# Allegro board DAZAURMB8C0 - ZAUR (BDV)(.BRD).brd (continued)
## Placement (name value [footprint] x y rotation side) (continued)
R194  HDT@1K_1%_2  [R0201]  117.79 48.73 0 top
R195  *1K_1%_2  [R0201]  114.74 48.5 90 top
R196  *2K_1%_2  [R0201]  115.45 48.5 270 top
R197  HDT@1K_1%_2  [R0201]  117.79 47.97 0 top
R198  TPC@100K_5%_4  [R0402]  23.94 47.87 180 top
R199  TPC@20K_1%_2  [R0201]  16.44 47.41 0 top
R200  **100K_1%_4  [R0402]  115.25 47.41 180 top
R201  *1K_1%_4  [R0402]  115.1 46.01 90 top
R202  **10K_5%_4  [R0402]  116.8 47.51 270 top
R203  HDT@1K_1%_2  [R0201]  117.79 46.98 0 top
R204  TPC@0_5%_2  [R0201]  22.03 46.34 180 top
R205  TPC_N@0_5%_2  [R0201]  22.48 46.34 0 top
R206  HDT@1K_1%_2  [R0201]  117.79 46.21 0 top
R207  TPC@0_5%_2  [R0201]  22.03 45.07 180 top
R208  TPC_N@0_5%_2  [R0201]  22.48 45.07 0 top
R209  HDT@10K_1%_2  [R0201]  117.41 44.44 0 top
R210  TSI@2.2K_5%_2  [R0201]  107.76 43.8 270 top
R211  TSI@2.2K_5%_2  [R0201]  108.52 43.8 270 top
R212  SP@0_5%_2  [R0201]  36.64 43.67 180 top
R213  SP@0_5%_2  [R0201]  37.65 43.67 180 top
R214  HDT@33_5%_2  [R0201]  113.85 44.18 90 top
R215  HDT@1K_1%_2  [R0201]  114.62 44.18 270 top
R216  HDT@10K_1%_2  [R0201]  117.41 43.67 0 top
R217  240_1%_2  [R0201]  41.21 43.04 180 top
R218  SP@0_5%_2  [R0201]  43.37 43.04 180 top
R219  HDT@33_5%_2  [R0201]  116.01 42.15 90 top
R220  HDT@1K_1%_2  [R0201]  116.77 42.15 270 top
R221  1K_1%_2  [R0201]  105.34 41.06 0 top
R222  100K_5%_2  [R0201]  148.91 40.88 90 top
R223  15K_1%_4  [R0402]  113.02 41.26 180 top
R224  10K_5%_2  [R0201]  105.34 40.3 0 top
R225  *10_5%_6  [R0603]  110.63 41.52 90 top
R226  10K_5%_2  [R0201]  103.06 39.99 0 top
R227  10K_5%_2  [R0201]  105.34 39.53 0 top
R228  10K_5%_2  [R0201]  103.06 39.23 0 top
R229  *Short_0201  [S0201]  22.54 38.47 180 top
R230  10K_5%_2  [R0201]  99.88 38.47 0 top
R231  TPC_N@10K_5%_4  [R0402]  104.33 38.21 270 top
R232  TPC@10K_5%_4  [R0402]  105.85 38.21 90 top
R233  0_2  [R0201]  152.59 37.96 90 top
R234  *Short_0201  [S0201]  22.54 37.45 180 top
R235  *Short_0201  [S0201]  103.19 37.2 0 top
R236  10K_5%_2  [R0201]  104.84 36.82 0 top
R237  *Short_0201  [S0201]  21.91 35.67 180 top
R238  *Short_0201  [S0201]  21.91 34.66 180 top
R239  33_5%_2  [R0201]  160.72 34.28 90 top
R240  *Short_0603  [S0603]  99.25 34.15 270 top
R241  10K_5%_2  [R0201]  92.77 33.64 270 top
R242  MD@10K_5%_2  [R0201]  93.53 33.64 90 top
R243  MD@10K_5%_2  [R0201]  94.3 33.64 270 top
R244  *0_5%_4  [R0402]  211.64 33.13 180 top
R245  2.2_5%_6  [R0603]  162.37 32.37 180 top
R246  *10K_5%_2  [R0201]  164.53 32.37 0 top
R247  10K_5%_2  [R0201]  174.69 32.37 180 top
R248  SP@0_5%_2  [R0201]  36.95 32.24 0 top
R249  SP@0_5%_2  [R0201]  37.94 32.24 0 top
R250  4.7K_5%_2  [R0201]  173.67 32.24 180 top
R251  *Short_0201  [S0201]  177.61 32.24 90 top
R252  *Short_0201  [S0201]  178.37 32.24 90 top
R253  *Short_0201  [S0201]  179.13 32.24 90 top
R254  *Short_0201  [S0201]  179.89 32.24 90 top
R255  10K_5%_2  [R0201]  181.04 32.24 90 top
R256  33_5%_2  [R0201]  183.2 32.24 0 top
R257  GS_N@10K_5%_4  [R0402]  100.9 32.12 0 top
R258  100K_5%_2  [R0201]  170.5 32.12 90 top
R259  4.7K_5%_2  [R0201]  171.26 32.12 90 top
R260  4.7K_5%_2  [R0201]  172.02 32.12 90 top
R261  1K_1%_4  [R0402]  102.8 31.99 180 top
R262  100K_5%_4  [R0402]  104.58 31.99 180 top
R263  *10K_5%_2  [R0201]  168.34 31.99 270 top
R264  *Short_0402  [S0402]  175.7 31.86 90 top
R265  *0_4  [R0402]  176.72 31.86 270 top
R266  MD@10K_5%_4  [R0402]  107.25 31.74 270 top
R267  MD@10K_5%_4  [R0402]  108.27 31.74 90 top
R268  *Short_0402  [S0402]  199.58 31.74 0 top
R269  33_5%_2  [R0201]  164.53 31.61 180 top
R270  4.7K_5%_2  [R0201]  173.67 31.48 180 top
R271  *0_5%_4  [R0402]  209.74 31.36 180 top
R272  10K_5%_2  [R0201]  96.96 31.23 270 top
R273  240_1%_2  [R0201]  40.19 30.85 180 top
R274  SP@0_5%_2  [R0201]  41.34 30.85 180 top
R275  *0_5%_4  [R0402]  209.74 30.09 180 top
R276  0_5%_8  [R0805]  190.05 29.78 180 top
R277  *Short_0402  [S0402]  105.73 29.45 270 top
R278  **MS@0_4  [R0402]  197.93 29.07 270 top
R279  10K_5%_2  [R0201]  101.41 28.94 270 top
R280  *Short_0603  [S0603]  96.33 28.69 0 top
R281  GS@10K_5%_4  [R0402]  100.52 28.56 90 top
R282  33_5%_2  [R0201]  183.53 29.15 180 top
R283  *10K_5%_2  [R0201]  159.45 28.56 180 top
R284  *10K_5%_2  [R0201]  159.45 27.8 0 top
R285  10K_5%_2  [R0201]  163.38 26.28 270 top
R286  2.2K_5%_2  [R0201]  71.82 27.16 270 top
R287  2.2K_5%_2  [R0201]  72.58 27.16 270 top
R288  *Short_0603  [S0603]  96.33 27.16 0 top
R289  45.3K_1%_4  [R0402]  103.19 26.91 90 top
R290  1.5K_5%_4  [R0402]  104.33 26.91 270 top
R291  *Short_0603  [S0603]  92.14 26.4 0 top
R292  *Short_0402  [S0402]  197.8 26.4 0 top
R293  **0_4  [R0402]  159.32 26.53 90 top
R294  10K_5%_2  [R0201]  94.3 26.15 180 top
R295  *Short_0603  [S0603]  87.67 26.02 0 top
R296  *Short_0201  [S0201]  100.77 25.89 180 top
R297  *Short_0603  [S0603]  84.64 25.77 0 top
R298  2.2_5%_6  [R0603]  162.24 25.59 90 top
R299  *0_5%_4  [R0402]  209.23 25.39 90 top
R300  EV@10K_5%_2  [R0201]  89.47 28.03 180 top
R301  *EV@0_5%_2  [R0201]  90.18 28.76 180 top
R302  *EV@Short_0201  [S0201]  91.2 25.26 0 top
R303  33_5%_2  [R0201]  184.06 25.13 0 top
R304  *Short_0201  [S0201]  197.8 25.13 180 top
R305  *2.2_5%_6  [R0603]  160.08 24.88 180 top
R306  *0_2  [R0201]  186.5 24.88 180 top
R307  *TPM@Short_0201  [S0201]  122.11 24.75 270 top
R308  *TPM@Short_0201  [S0201]  122.87 24.75 270 top
R309  *Short_0201  [S0201]  187.51 24.75 0 top
R310  10K_5%_2  [R0201]  188.53 24.75 0 top
R311  TPM@33_5%_2  [R0201]  121.22 24.37 0 top
R312  TPM@0_4  [R0402]  132.14 24.12 270 top
R313  *10K_5%_4  [R0402]  105.22 23.99 0 top
R314  *TPC@Short_0201  [S0201]  25.08 23.86 180 top
R315  *100K_1%_2  [R0201]  197.8 23.86 180 top
R316  TPM@10K_5%_2  [R0201]  121.22 23.35 0 top
R317  *256@0_5%_2  [R0201]  200.72 23.35 0 top
R318  *255@0_5%_2  [R0201]  201.74 23.35 180 top
R319  33_5%_2  [R0201]  185.23 23.1 180 top
R320  **MS@0_4  [R0402]  199.2 23.1 270 top
R321  *TPM@Short_0201  [S0201]  121.22 22.59 0 top
R322  *22_5%_4  [R0402]  162.88 22.72 180 top
R323  *TPM@0_4  [R0402]  132.52 22.34 90 top
R324  *Short_0201  [S0201]  185.35 22.34 0 top
R325  TPM@33_5%_2  [R0201]  120.97 21.83 0 top
R326  *10_5%_6  [R0603]  149.54 21.83 180 top
R327  *10K_5%_2  [R0201]  200.85 21.83 180 top
R328  *Short_0402  [S0402]  206.55 21.83 180 top
R329  *255@0_5%_4  [R0402]  199.32 21.7 180 top
R330  *Short_0201  [S0201]  153.22 21.45 90 top
R331  100K_5%_4  [R0402]  158.3 21.96 0 top
R332  TPC@100K_5%_4  [R0402]  183.96 21.45 180 top
R333  *TPM@1.2K_5%_2  [R0201]  129.6 21.32 270 top
R334  1K_5%_2  [R0201]  201.53 20.94 270 top
R335  *TPC@Short_0402  [S0402]  20.51 20.69 0 top
R336  *TPC@4.7K_5%_2  [R0201]  15.05 20.56 270 top
R337  *TPC@Short_0201  [S0201]  15.81 20.56 90 top
R338  *TPC@10K_5%_2  [R0201]  16.7 20.56 90 top
R339  TPC_N@100K_5%_4  [R0402]  183.96 20.43 0 top
R340  *GS@Short_0402  [S0402]  61.91 20.31 180 top
R341  TPC@10K_5%_4  [R0402]  17.71 20.18 270 top
R342  TPC@10K_5%_4  [R0402]  18.73 20.18 270 top
R343  *TPM@0_4  [R0402]  131.89 20.05 90 top
R344  *Short_0603  [S0603]  199.86 20.13 180 top
R345  *TPC@Short_0201  [S0201]  24.19 19.8 180 top
R346  100K_5%_4  [R0402]  147.51 19.67 90 top
R347  10K_5%_4  [R0402]  153.22 19.67 270 top
R348  4.7K_5%_2  [R0201]  71.31 19.58 180 top
R349  4.7K_5%_2  [R0201]  72.45 19.58 0 top
R350  TPM@10K_5%_2  [R0201]  121.22 19.04 0 top
R351  100K_5%_2  [R0201]  159.57 18.4 270 top
R352  *Short_0201  [S0201]  160.46 18.53 0 top
R353  **MS@0_4  [R0402]  203.8 19.32 0 top
R354  256@0_5%_4  [R0402]  205.8 18.66 180 top
R355  TPC@220K_5%_2  [R0201]  13.4 18.53 90 top
R356  TPM@0_4  [R0402]  131.51 18.53 0 top
R357  *GS@Short_0201  [S0201]  68.64 18.38 270 top
R358  TPM@33_5%_2  [R0201]  121.22 18.27 0 top
R359  *Short_0603  [S0603]  115.43 17.97 270 top
R360  *Short_0603  [S0603]  116.9 17.97 270 top
R361  *Short_0603  [S0603]  118.32 17.97 270 top
R362  *Short_0603  [S0603]  119.75 17.97 270 top
R363  TPC@220K_5%_2  [R0201]  13.4 17.51 270 top
R364  4.7K_5%_2  [R0201]  205.17 17.44 180 top
R365  *4.7K_5%_2  [R0201]  206.18 17.51 180 top
R366  TPC@6.2K_1%_2  [R0201]  22.41 17.39 0 top
R367  ODD@10K_5%_4  [R0402]  129.09 17.51 0 top
R368  *MS@100K_5%_4  [R0402]  188.02 17.39 180 top
R369  100K_5%_2  [R0201]  183.07 17.26 0 top
R370  *255@0_5%_4  [R0402]  204.1 17.23 270 top
R371  4.7K_5%_2  [R0201]  205.17 16.72 180 top
R372  *4.7K_5%_2  [R0201]  206.18 16.75 180 top
R373  TPC@200K_1%_2  [R0201]  23.53 16.62 0 top
R374  TPC@10K_1%_2  [R0201]  22.64 16.5 90 top
R375  *ODD@10K_5%_4  [R0402]  126.5 16.88 270 top
R376  *Short_0201  [S0201]  70.93 16.27 180 top
R377  *Short_0201  [S0201]  72.83 16.27 180 top
R378  *GS@10K_5%_2  [R0201]  68.9 16.24 0 top
R379  *GS@Short_0201  [S0201]  68.01 15.99 90 top
R380  *4.7K_5%_2  [R0201]  204.4 15.99 180 top
R381  4.7K_5%_2  [R0201]  206.18 15.99 180 top
R382  ODD@0_5%_8  [R0805]  142.56 15.73 270 top
R383  TPC@220K_5%_2  [R0201]  12.13 15.66 90 top
R384  100K_5%_2  [R0201]  163.38 15.61 90 top
R385  10K_5%_4  [R0402]  159.83 15.23 90 top
R386  *GS@10K_5%_2  [R0201]  66.48 15.23 270 top
R387  *GS@Short_0201  [S0201]  67.24 15.23 90 top
R388  ODD@33_5%_2  [R0201]  127.19 15.23 270 top
R389  *4.7K_5%_2  [R0201]  204.4 15.23 180 top
R390  4.7K_5%_2  [R0201]  206.18 15.23 180 top
R391  TPC@10K_5%_4  [R0402]  22.92 15.1 270 top
R392  TPC@4.7K_5%_2  [R0201]  23.94 15.1 270 top
R393  *ODD@100K_5%_4  [R0402]  150.94 15.1 90 top
R394  *0_2  [R0201]  71.31 14.92 90 top
R395  *0_2  [R0201]  72.45 14.92 90 top
R396  TPC@220K_5%_2  [R0201]  12.13 14.64 270 top
R397  *10K_5%_2  [R0201]  198.82 14.59 0 top
R398  *4.7K_5%_2  [R0201]  204.4 14.46 180 top
R399  4.7K_5%_2  [R0201]  206.18 14.46 180 top
R400  0_5%_8  [R0805]  214.26 15.35 270 top
R401  TPC@750K_1%_4  [R0402]  14.54 14.08 0 top
R402  *MS@100K_5%_4  [R0402]  201.1 14.64 0 top
R403  *0_2  [R0201]  192.34 13.96 180 top
R404  **MS@10K_5%_4  [R0402]  203.26 13.83 270 top
R405  TPC@10K_5%_2  [R0201]  24.83 13.7 180 top
R406  *4.7K_5%_2  [R0201]  204.66 13.58 180 top
R407  4.7K_5%_2  [R0201]  206.18 13.58 180 top
R408  TPC@750K_1%_4  [R0402]  14.54 12.94 0 top
R409  10K_5%_2  [R0201]  192.21 12.94 270 top
R410  4.7K_5%_2  [R0201]  204.66 12.69 180 top
R411  *4.7K_5%_2  [R0201]  206.18 12.69 180 top
R412  33_5%_2  [R0201]  183.58 12.56 0 top
R413  **ODD@10K_5%_4  [R0402]  146.24 12.18 90 top
R414  *ODD@100K_5%_4  [R0402]  147.38 12.18 270 top
R415  TPC@750K_1%_4  [R0402]  15.94 11.67 90 top
R416  TPC@750K_1%_4  [R0402]  17.08 11.67 90 top
R417  *Short_0402  [S0402]  204.66 11.67 180 top
R418  *TPC@Short_0201  [S0201]  11.19 11.64 180 top
R419  *TPC@Short_0201  [S0201]  11.19 10.93 180 top
R420  *MS@100K_5%_4  [R0402]  210.88 10.65 0 top
R421  *SSD@0_2  [R0201]  17.44 9.64 90 top
R422  *SSD@100K_5%_2  [R0201]  14.41 9.38 180 top
R423  *Short_0201  [S0201]  23.43 9.13 90 top
R424  SSD@0_2  [R0201]  17.33 8.37 90 top
R425  SSD@100K_5%_2  [R0201]  23.43 8.11 270 top
R426  SSD@0_5%_8  [R0805]  12.25 7.48 90 top
R427  *SSD@10K_5%_2  [R0201]  17.33 7.35 90 top
R428  SSD@0_2  [R0201]  21.91 7.35 90 top
R429  *SSD@0_2  [R0201]  21.91 6.34 270 top
R430  *SSD@10K_5%_4  [R0402]  31.81 5.4 270 top
R431  *Short_0201  [S0201]  26.1 5.19 0 top
R432  *SSD@SSD@100K_5%_2  [R0201]  26.35 4.18 90 top
R433  SSD@0_2  [R0201]  27.11 4.18 270 top
R434  SSD@100K_5%_2  [R0201]  31.3 3.03 0 top
R435  *SSD@0_2  [R0201]  24.57 2.53 0 top
R436  *EV@47K_1%_2  [R0201]  110.42 124.83 270 bottom
R437  EV@5.1K/F_2  [R0201]  113.73 124.7 180 bottom
R438  *EV@5.1K/F_2  [R0201]  113.73 123.94 180 bottom
R439  *EV@Short_0201  [S0201]  110.42 123.81 90 bottom
R440  *EV@5.1K/F_2  [R0201]  117.92 122.92 270 bottom
R441  *EV@5.1K/F_2  [R0201]  113.73 122.8 180 bottom
R442  EV@1M_1%_2  [R0201]  104.46 122.41 180 bottom
R443  *EV@5.1K/F_2  [R0201]  113.73 122.03 180 bottom
R444  EV@10K_5%_2  [R0201]  115.25 122.03 0 bottom
R445  EV@5.1K/F_2  [R0201]  117.79 122.03 0 bottom
R446  EV@4.7K_5%_2  [R0201]  107.5 121.78 180 bottom
R447  EV@4.7K_5%_2  [R0201]  108.52 121.78 180 bottom
R448  2.2_5%_4  [R0402]  39.3 121.53 270 bottom
R449  *EV@1K_1%_2  [R0201]  112.46 121.27 0 bottom
R450  *EV@5.1K/F_2  [R0201]  113.73 121.27 180 bottom
R451  *EV@5.1K/F_2  [R0201]  115.25 121.27 0 bottom
R452  EV@5.1K/F_2  [R0201]  116.52 121.27 180 bottom
R453  EV@5.1K/F_2  [R0201]  118.04 121.27 0 bottom
R454  EV@5.1K/F_2  [R0201]  119.31 121.27 180 bottom
R455  *EV@Short_0201  [S0201]  107.5 121.02 180 bottom
R456  *EV@Short_0201  [S0201]  108.52 121.02 180 bottom
R457  EV@120_1%_4  [R0402]  137.22 120.64 180 bottom
R458  EV@10K_5%_2  [R0201]  112.46 120.51 0 bottom
R459  EV@5.1K/F_2  [R0201]  113.73 120.51 180 bottom
R460  EV@5.1K/F_2  [R0201]  115.25 120.51 0 bottom
R461  *EV@5.1K/F_2  [R0201]  116.52 120.51 180 bottom
R462  EV@5.1K/F_2  [R0201]  118.04 120.51 0 bottom
R463  *EV@5.1K/F_2  [R0201]  119.31 120.51 180 bottom
R464  *EV@10K_5%_2  [R0201]  105.85 120.48 270 bottom
R465  *EV@10K_5%_2  [R0201]  106.61 120.48 270 bottom
R466  EV@10K_5%_2  [R0201]  108.39 120.13 0 bottom
R467  *EV@5.1K_1%_2  [R0201]  109.79 120.13 0 bottom
R468  EV@5.1K/F_2  [R0201]  112.46 119.75 0 bottom
R469  *EV@5.1K/F_2  [R0201]  113.73 119.75 180 bottom
R470  EV@5.1K/F_2  [R0201]  115.25 119.75 0 bottom
R471  *EV@5.1K/F_2  [R0201]  116.52 119.75 180 bottom
R472  EV@5.1K/F_2  [R0201]  118.04 119.75 0 bottom
R473  EV@5.1K/F_2  [R0201]  119.31 119.75 180 bottom
R474  *EV@10K_5%_2  [R0201]  108.39 119.37 0 bottom
R475  EV@1K_1%_2  [R0201]  109.79 119.37 180 bottom
R476  EV@5.1K/F_2  [R0201]  121.09 119.37 180 bottom
R477  EV@5.1K/F_2  [R0201]  124.39 119.37 180 bottom
R478  EV@5.1K_1%_2  [R0201]  102.17 119.24 270 bottom
R479  *EV@5.1K_1%_2  [R0201]  103.19 119.24 270 bottom
R480  *EV@Short_0201  [S0201]  104.58 119.11 0 bottom
R481  EV@200_1%_2  [R0201]  106.64 118.99 90 bottom
R482  *EV@5.1K/F_2  [R0201]  112.53 119.04 0 bottom
R483  EV@5.1K/F_2  [R0201]  113.78 118.99 180 bottom
R484  *EV@5.1K/F_2  [R0201]  115.25 118.99 0 bottom
R485  EV@5.1K/F_2  [R0201]  116.52 118.99 180 bottom
R486  EV@5.1K/F_2  [R0201]  118.04 118.99 0 bottom
R487  EV@5.1K/F_2  [R0201]  119.31 118.99 180 bottom
R488  *EV@100K_5%_4  [R0402]  58.1 118.86 180 bottom
R489  *EV@Short_0201  [S0201]  105.78 118.86 0 bottom
R490  *EV@5.1K/F_2  [R0201]  121.09 118.6 180 bottom
R491  *EV@5.1K/F_2  [R0201]  124.39 118.6 180 bottom
R492  *EV@16.2K_4  [R0402]  97.6 118.48 0 bottom
R493  *Short_0402  [S0402]  39.69 118.22 0 bottom
R494  *S_1206  [S1206]  94.68 117.08 270 bottom
R495  EV@2.37K_1%_2  [R0201]  130.24 114.16 0 bottom
R496  *R18M-50@4.75K_1%_4  [R0402]  96.71 113.52 180 bottom
R497  EV@5.49K_1%_2  [R0201]  130.24 113.4 0 bottom
R498  *R18M-50@0_5%_4  [R0402]  96.71 112.51 0 bottom
R499  *R18M-50@6.98K_1%_4  [R0402]  96.76 111.37 0 bottom
R500  *R18M-50@4.75K_1%_4  [R0402]  96.76 110.35 180 bottom
R501  *R18M-50@2K_1%_4  [R0402]  96.71 105.65 0 bottom
R502  *Short_0201  [S0201]  46.54 105.4 90 bottom
R503  *Short_0201  [S0201]  47.31 105.4 90 bottom
R504  33_5%_2  [R0201]  55.81 105.17 180 bottom
R505  33_5%_2  [R0201]  56.83 105.14 180 bottom
R506  33_5%_2  [R0201]  57.85 105.14 180 bottom
R507  *R18M-50@8.45K_1%_4  [R0402]  96.71 104.63 180 bottom
R508  0_5%_6  [R0603]  59.75 104.38 270 bottom
R509  *MS@0_5%_6  [R0603]  61.17 104.38 90 bottom
R510  *100K_1%_4  [R0402]  54.04 103.87 90 bottom
R511  *100K_1%_4  [R0402]  55.18 103.87 90 bottom
R512  *R18M-50@8.45K_1%_4  [R0402]  96.71 103.62 180 bottom
R513  TSI@0_2  [R0201]  45.65 103.59 270 bottom
R514  TSI@0_2  [R0201]  46.67 103.59 270 bottom
R515  *TSU@0_2  [R0201]  45.65 103.14 90 bottom
R516  *TSU@0_2  [R0201]  46.67 103.14 90 bottom
R517  *R18M-50@2K_1%_4  [R0402]  96.71 102.6 0 bottom
R518  EV@1K_1%_2  [R0201]  140.67 102.24 180 bottom
R519  *MS@0_4  [R0402]  60.64 101.97 0 bottom
R520  EV@150_1%_2  [R0201]  96.71 98.16 180 bottom
R521  EV@1K_1%_2  [R0201]  140.79 97.39 180 bottom
R522  EV@1K_1%_2  [R0201]  94.42 96.89 0 bottom
R523  EV@1K_1%_2  [R0201]  95.57 96.89 0 bottom
R524  *EV@1K_1%_2  [R0201]  96.71 96.89 180 bottom
R525  100K_5%_4  [R0402]  67.12 94.86 180 bottom
R526  EV@2.37K_1%_2  [R0201]  130.49 90.66 0 bottom
R527  100K_5%_4  [R0402]  66.86 90.03 0 bottom
R528  EV@5.49K_1%_2  [R0201]  130.49 89.9 0 bottom
R529  *Short_0201  [S0201]  67.5 89.01 180 bottom
R530  EV@10K_5%_2  [R0201]  123.89 88.63 180 bottom
R531  *10K_1%_2  [R0201]  84.52 84.95 90 bottom
R532  *10K_1%_2  [R0201]  85.28 84.95 90 bottom
R533  100K_5%_2  [R0201]  87.82 83.43 270 bottom
R534  10K_5%_2  [R0201]  22.19 83.17 90 bottom
R535  *4.7K_5%_2  [R0201]  18.22 82.79 90 bottom
R536  *4.7K_5%_2  [R0201]  21.17 82.84 270 bottom
R537  *10K_1%_2  [R0201]  84.52 82.79 90 bottom
R538  *10K_1%_2  [R0201]  85.41 82.79 90 bottom
R539  *10K_5%_2  [R0201]  19.37 82.66 270 bottom
R540  *10K_5%_2  [R0201]  20.13 82.66 270 bottom
R541  1K_1%_2  [R0201]  89.09 82.54 90 bottom
R542  *Short_0603  [S0603]  16.06 82.39 90 bottom
R543  *Short_0201  [S0201]  87.82 82.28 90 bottom
R544  *Short_0603  [S0603]  95.06 81.65 0 bottom
R545  *Short_0603  [S0603]  95.06 80.12 0 bottom
R546  *Short_0201  [S0201]  87.82 81.14 270 bottom
R547  EV@2.37K_1%_2  [R0201]  145.25 79.77 90 bottom
R548  EV@5.49K_1%_2  [R0201]  146.24 79.77 90 bottom
R549  *1K_1%_2  [R0201]  84.01 79.74 270 bottom
R550  *1K_1%_2  [R0201]  84.77 79.74 270 bottom
R551  *1K_1%_2  [R0201]  85.91 79.74 270 bottom
R552  2.2K_5%_2  [R0201]  86.8 79.87 90 bottom
R553  EV@5.49K_1%_2  [R0201]  142.05 79.65 90 bottom
R554  EV@2.37K_1%_2  [R0201]  143.35 79.65 90 bottom
R555  EV@120_1%_4  [R0402]  139.89 79.48 270 bottom
R556  1K_1%_2  [R0201]  87.69 79.23 270 bottom
R557  2.2K_5%_2  [R0201]  88.58 79.23 90 bottom
R558  2.2K_5%_2  [R0201]  89.34 79.23 90 bottom
R559  *1K_1%_2  [R0201]  87.69 78.22 90 bottom
R560  100K_5%_2  [R0201]  88.58 78.22 270 bottom
R561  100K_5%_2  [R0201]  89.34 78.22 270 bottom
R562  1K_1%_2  [R0201]  83.55 78.09 90 bottom
R563  22_1%_2  [R0201]  84.31 78.09 90 bottom
R564  *Short_0201  [S0201]  85.05 78.09 90 bottom
R565  22_1%_2  [R0201]  85.79 78.09 90 bottom
R566  100K_5%_2  [R0201]  86.55 78.09 270 bottom
R567  100K_5%_2  [R0201]  90.87 78.09 270 bottom
R568  4.7K_5%_2  [R0201]  21.52 73.27 270 bottom
R569  4.7K_5%_2  [R0201]  22.54 72.5 90 bottom
R570  196_1%_4  [R0402]  108.52 62.22 180 bottom
R571  10K_5%_2  [R0201]  108.01 61.2 90 bottom
R572  10K_5%_2  [R0201]  108.9 61.2 90 bottom
R573  TPC_N@0_5%_8  [R0805]  20.13 56.76 180 bottom
R574  TPC_N@0_5%_8  [R0805]  20 53.45 180 bottom
R575  *EV@Short_0201  [S0201]  108.14 52.95 180 bottom
R576  10K_5%_2  [R0201]  110.42 52.82 0 bottom
R577  *EV@Short_0201  [S0201]  108.14 52.18 180 bottom
R578  1K_1%_2  [R0201]  73.09 51.8 180 bottom
R579  *Short_0201  [S0201]  110.42 51.8 180 bottom
R580  *Short_0201  [S0201]  110.42 51.04 180 bottom
R581  *Short_0201  [S0201]  108.14 50.66 180 bottom
R582  *Short_0201  [S0201]  108.14 49.9 180 bottom
R583  *Short_0201  [S0201]  110.42 49.64 180 bottom
R584  *Short_0201  [S0201]  110.42 48.75 180 bottom
R585  33_5%_2  [R0201]  108.39 48.07 180 bottom
R586  10K_5%_2  [R0201]  110.42 47.99 0 bottom
R587  33_5%_2  [R0201]  108.39 47.36 180 bottom
R588  33_5%_2  [R0201]  108.39 46.6 180 bottom
R589  10K_5%_2  [R0201]  110.42 46.34 0 bottom
R590  33_5%_2  [R0201]  108.39 45.83 180 bottom
R591  10K_5%_2  [R0201]  108.39 44.94 0 bottom
R592  *2K_1%_2  [R0201]  110.04 44.31 270 bottom
R593  10K_5%_2  [R0201]  110.81 44.31 270 bottom
R594  10K_5%_2  [R0201]  108.39 44.06 0 bottom
R595  4.7K_5%_2  [R0201]  107.5 43.17 180 bottom
R596  *HDT@Short_0402  [S0402]  108.77 42.79 270 bottom
R597  4.7K_5%_2  [R0201]  107.5 42.4 180 bottom
R598  HDT@1K_1%_2  [R0201]  110.68 41.36 0 bottom
R599  *HDT@Short_0201  [S0201]  110.55 40.63 180 bottom
R600  20M_5%_4  [R0402]  106.36 39.61 90 bottom
R601  MD@10K_5%_4  [R0402]  112 39.15 180 top
R602  200K_1%_2  [R0201]  116.14 38.59 0 bottom
R603  HDT@10K_1%_2  [R0201]  118.81 38.47 0 bottom
R604  MD@10K_5%_4  [R0402]  110.22 39.69 180 top
R605  *0_2  [R0201]  19.87 38.44 180 bottom
R606  *10K_5%_4  [R0402]  207.71 37.58 270 bottom
R607  47_1%_4  [R0402]  209.1 37.58 0 bottom
R608  47_1%_4  [R0402]  210.88 37.58 0 bottom
R609  4.7K_5%_2  [R0201]  206.44 37.45 0 bottom
R610  1M_5%_2  [R0201]  106.61 36.69 0 bottom
R611  *Short_0201  [S0201]  98.92 34.28 0 bottom
R612  4.7K_5%_2  [R0201]  209.1 36.18 270 bottom
R613  *10K_5%_4  [R0402]  210.63 36.18 180 bottom
R614  22_1%_2  [R0201]  90.21 35.65 90 bottom
R615  *47K_1%_2  [R0201]  91.88 35.93 270 bottom
R616  10_1%_2  [R0201]  92.64 35.93 270 bottom
R617  10_1%_2  [R0201]  93.41 35.93 270 bottom
R618  *10K_5%_2  [R0201]  94.17 35.93 270 bottom
R619  33_5%_2  [R0201]  95.03 35.93 90 bottom
R620  22_1%_2  [R0201]  95.77 35.29 90 bottom
R621  *Short_0201  [S0201]  96.89 35.65 0 bottom
R622  10_1%_2  [R0201]  97.75 34.45 90 bottom
R623  *TPM@10K_5%_2  [R0201]  98.92 35.27 180 bottom
R624  *Short_0201  [S0201]  99.86 35.14 270 bottom
R625  *TPM_N@10K_5%_2  [R0201]  100.65 35.93 270 bottom
R626  *Short_0201  [S0201]  101.41 35.93 270 bottom
R627  *0_5%_2  [R0201]  102.17 35.93 90 bottom
R628  33_5%_2  [R0201]  103.36 35.67 180 bottom
R629  TPM@0_2  [R0201]  98.92 33.51 180 bottom
R630  *255@0_5%_4  [R0402]  204.15 35.17 270 bottom
R631  256@0_5%_4  [R0402]  205.17 35.17 270 bottom
R632  2.2K_5%_2  [R0201]  209.23 35.17 0 bottom
R633  10K_5%_2  [R0201]  202.25 34.91 270 bottom
R634  22K_5%_4  [R0402]  200.98 34.68 0 bottom
R635  10_1%_2  [R0201]  90.33 34.38 270 bottom
R636  *Short_0201  [S0201]  101.66 34.66 270 bottom
R637  *10K_5%_2  [R0201]  159.83 34.4 180 bottom
R638  *Short_0201  [S0201]  160.84 34.33 0 bottom
R639  *Short_0201  [S0201]  161.99 34.4 180 bottom
R640  *10K_1%_2  [R0201]  93.86 34.28 270 bottom
R641  10K_5%_2  [R0201]  96.81 34.05 180 bottom
R642  2.2K_5%_2  [R0201]  209.23 33.26 0 bottom
R643  IV@10K_5%_4  [R0402]  91.76 32.63 0 bottom
R644  10_1%_2  [R0201]  93.66 31.86 270 bottom
R645  *short_6  [S0603]  204.79 32.63 270 bottom
R646  *2K_1%_2  [R0201]  96.96 32.37 180 bottom
R647  100K_5%_4  [R0402]  199.96 32.24 270 bottom
R648  EV@10K_5%_4  [R0402]  91.76 31.61 180 bottom
R649  10K_5%_2  [R0201]  97.22 31.61 0 bottom
R650  *Short_0201  [S0201]  98.23 31.61 180 bottom
R651  200K_1%_4  [R0402]  200.98 31.61 270 bottom
R652  *0_5%_2  [R0201]  97.22 30.85 0 bottom
R653  *0_5%_2  [R0201]  98.23 30.85 180 bottom
R654  *256@0_5%_2  [R0201]  198.05 30.57 270 bottom
R655  *256@0_5%_2  [R0201]  197.8 29.58 180 bottom
R656  *255@0_5%_2  [R0201]  197.8 28.82 180 bottom
R657  100K_5%_4  [R0402]  208.72 28.69 0 bottom
R658  2.2K_5%_2  [R0201]  85.91 28.56 90 bottom
R659  2.2K_5%_2  [R0201]  87.06 28.56 90 bottom
R660  *0_5%_2  [R0201]  85.91 27.55 270 bottom
R661  *Short_0201  [S0201]  87.06 27.55 270 bottom
R662  33_5%_2  [R0201]  197.8 27.29 180 bottom
R663  TPM_N@10K_5%_4  [R0402]  88.07 26.91 90 bottom
R664  MD@10K_5%_4  [R0402]  88.28 23.84 0 top
R665  *Short_0603  [S0603]  82.1 26.15 270 bottom
R666  *Short_0603  [S0603]  83.63 26.15 270 bottom
R667  *10K_5%_2  [R0201]  162.11 29.45 270 top
R668  *Short_0201  [S0201]  162.11 28.43 90 top
R669  *Short_0201  [S0201]  164.91 26.53 0 bottom
R670  *Short_0201  [S0201]  70.8 25.34 0 bottom
R671  4.7K_5%_2  [R0201]  74.89 25.31 0 bottom
R672  MD@10K_5%_4  [R0402]  86.52 23.84 0 top
R673  TPM@10K_5%_4  [R0402]  87.67 24.78 0 bottom
R674  4.7K_5%_2  [R0201]  72.2 24.75 180 bottom
R675  10K_5%_4  [R0402]  164.65 33.64 0 bottom
R676  *Short_0201  [S0201]  166.18 34.4 90 bottom
R677  *Short_0201  [S0201]  71.18 24.37 90 bottom
R678  **MS@0_5%_6  [R0603]  194.27 24.09 90 bottom
R679  10K_5%_2  [R0201]  170.88 20.81 180 bottom
R680  22_1%_2  [R0201]  198.05 23.99 180 bottom
R681  *10K_5%_4  [R0402]  70.29 23.35 270 bottom
R682  *Short_0201  [S0201]  71.18 23.35 90 bottom
R683  *10K_5%_2  [R0201]  158.94 23.1 90 top
R684  10K_5%_2  [R0201]  176.46 23.23 180 bottom
R685  *Short_0201  [S0201]  198.05 23.23 0 bottom
R686  *10K_5%_4  [R0402]  66.23 22.59 270 bottom
R687  *Short_0201  [S0201]  67.75 22.21 0 bottom
R688  *PBA@Short_0402  [S0402]  54.67 21.83 180 bottom
R689  1K_5%_2  [R0201]  176.34 21.58 90 bottom
R690  10K_5%_2  [R0201]  177.1 21.58 270 bottom
R691  100K_5%_2  [R0201]  163.13 19.67 90 top
R692  *PBA@0_5%_4  [R0402]  51.14 19.67 270 top
R693  *Short_0201  [S0201]  205.55 19.93 90 bottom
R694  PBA@10K_5%_4  [R0402]  52.92 15.15 270 bottom
R695  *TPC@0_4  [R0402]  13.4 19.42 180 bottom
R696  *0_2  [R0201]  192.52 20.2 90 bottom
R697  33_5%_2  [R0201]  173.67 19.42 90 bottom
R698  0_2  [R0201]  177.86 21.58 90 bottom
R699  256@0_5%_4  [R0402]  205.55 17.79 270 bottom
R700  *TPC@Short_0402  [S0402]  19.37 18.15 0 bottom
R701  *Short_0201  [S0201]  210.91 17.77 180 bottom
R702  *DBG@Short_0201  [S0201]  192.75 17.51 0 bottom
R703  KBL@10K_5%_4  [R0402]  196.4 17.51 90 bottom
R704  *MS@100K_5%_4  [R0402]  181.04 21.07 90 bottom
R705  GS_N@0_5%_2  [R0201]  212.41 17.39 180 bottom
R706  *DBG@Short_0201  [S0201]  192.59 16.62 90 bottom
R707  GS@0_5%_2  [R0201]  212.41 16.67 180 bottom
R708  *10K_5%_4  [R0402]  208.34 16.5 0 bottom
R709  *TPC@10K_5%_4  [R0402]  20.38 16.37 270 bottom
R710  *TPC@10K_5%_4  [R0402]  21.4 16.37 90 bottom
R711  *PBA@Short_0402  [S0402]  52.77 17.39 0 bottom
R712  *DBG@Short_0201  [S0201]  192.59 15.61 90 bottom
R713  *TPC@10K_5%_4  [R0402]  13.02 15.35 270 bottom
R714  *TPC@10K_5%_4  [R0402]  14.03 15.35 90 bottom
R715  *0_2  [R0201]  209.87 14.97 0 bottom
R716  *DBG@Short_0201  [S0201]  180.91 14.72 0 bottom
R717  *33K_1%_4  [R0402]  212.41 14.72 90 bottom
R718  *33K_1%_4  [R0402]  210.88 14.46 270 bottom
R719  *DBG@Short_0201  [S0201]  180.91 13.96 0 bottom
R720  *TPC@Short_0402  [S0402]  15.3 12.69 270 bottom
R721  *Short_0201  [S0201]  32.22 11.64 270 bottom
R722  *Short_0201  [S0201]  32.98 11.64 270 bottom
R723  *Short_0201  [S0201]  29.27 11.54 270 bottom
R724  *Short_0201  [S0201]  30.03 11.54 270 bottom
R725  *Short_0201  [S0201]  38.29 11.54 270 bottom
R726  *Short_0201  [S0201]  39.05 11.54 270 bottom
R727  *Short_0201  [S0201]  26.33 11.52 270 bottom
R728  *Short_0201  [S0201]  27.06 11.52 270 bottom
R729  *Short_0201  [S0201]  35.22 11.52 270 bottom
R730  *Short_0201  [S0201]  35.98 11.52 270 bottom
R731  *0_2  [R0201]  112.43 46.52 180 top
R732  *Short_0201  [S0201]  113.45 46.52 0 top
R733  100K_5%_2  [R0201]  173.26 12.66 0 top
R734  **10K_5%_4  [R0402]  78.17 123.33 270 top
R735  **10K_5%_4  [R0402]  88.07 124.45 270 top
R736  1K_1%_2  [R0201]  31.76 64.68 180 top
R737  1K_1%_2  [R0201]  31.76 65.44 0 top
R738  *0_5%_6  [R0603]  30.49 64.96 270 top
R739  *Short_0402  [S0402]  36.26 6.84 270 top
R740  *Short_0402  [S0402]  35.24 6.84 270 top
R741  *Short_0402  [S0402]  34.48 9.26 270 top
R742  *Short_0402  [S0402]  33.46 9.26 270 top
R743  *Short_0402  [S0402]  31.56 9.38 270 top
R744  *Short_0402  [S0402]  30.54 9.38 270 top
R745  *Short_0402  [S0402]  28.64 9.38 270 top
R746  *Short_0402  [S0402]  27.62 9.38 270 top
R747  0_4  [R0402]  197.47 16.39 90 top
R748  *10K_5%_2  [R0201]  110.42 47.28 0 bottom
RV1  *TVM0G5R5M220R_22p  [R0402]  13.65 87.24 270 top
RV2  *TVM0G5R5M220R_22p  [R0402]  15.43 87.24 270 top
RV3  TPC@MESD3324PCR  [SON10-2_5X1-5-0_55H]  10.22 16.12 90 top
RV5  *TVM0G5R5M220R_22p  [R0402]  14.79 82.41 270 bottom
RV6  *TVM0G5R5M220R_22p  [R0402]  14.69 80.5 90 bottom
RV7  TPC@MESD3324PCR  [SON10-2_5X1-5-0_55H]  10.22 16.12 270 bottom
RV8  TPC@PESD5V0F1BSF  [D-0_6X0_3-0_32H-SMT]  7.58 14.82 90 top
RV9  TPC@PESD5V0F1BSF  [D-0_6X0_3-0_32H-SMT]  8.52 15.63 90 top
SW1  RESET_SW  [SW-TME-532-V-6P]  64.85 100.9 270 bottom
SW2  *NDT016-G1A-KKKT  [SW-NDT016-G1A-KKKT-4P]  19.1 60.62 180 bottom
SW3  *T3AL-23S-Q-T/R  [SW-T3AL-23-Q-TR-4P]  164.78 36.82 0 bottom
TP1  *PAD  [TP2050]  107.76 124.07 0 top
TP2  *  [TP2650]  119.57 123.71 0 top
TP3  *PAD  [TP2050]  105.6 123.05 0 top
TP4  *PAD  [TP2050]  117.79 123.05 0 top
TP5  *PAD  [TP2050]  107.76 122.41 0 top
TP6  *PAD  [TP2050]  118.68 121.4 0 top
TP7  *  [TP2650]  120.03 120.64 0 top
TP8  *PAD  [TP2050]  123.76 119.49 0 top
TP9  *  [TP2650]  110.93 118.73 0 top
TP10  *  [TP2050]  49.72 111.11 180 top
TP11  *  [TP2050]  46.62 110.4 180 top
TP12  *  [TP2050]  45.55 108.65 180 top
TP13  *PAD  [TP2050]  97.34 102.35 0 top
TP14  *PAD  [TP2050]  97.34 101.08 0 top
TP15  *PAD  [TP2050]  97.47 99.55 0 top
TP16  *PAD  [TP2050]  96.45 98.67 0 top
TP17  *PAD_NC  [TP2050]  68.13 65.01 0 top
TP18  *TP  [TP2050]  84.14 58.08 0 top
TP19  *PAD_NC  [TP2050]  84.14 56.12 0 top
TP20  *PAD  [TP2050]  52.13 54.04 0 top
TP21  *PAD_NC  [TP2050]  99.38 52.06 0 top
TP22  *PAD_NC  [TP2050]  106.87 43.42 0 top
TP23  *PAD_NC  [TP2050]  105.73 42.66 0 top
TP24  *PAD_NC  [TP2050]  96.45 35.17 0 top
TP25  *  [TP2075]  138.18 31.55 0 top
TP27  *PAD_NC  [TP2050]  171.49 31.23 0 top
TP28  *TP  [TP2050]  182.56 30.21 0 top
TP30  *TP  [TP2050]  164.02 27.93 0 top
TP33  *  [TP2050]  200.21 24.12 270 top
TP34  *  [TP2050]  202.63 23.35 270 top
TP35  *TP  [TP2050]  164.15 22.08 0 top
TP36  *TP  [TP2050]  182.69 21.32 0 top
TP37  *  [TP2675]  14.06 19.52 0 top
TP39  *PAD  [TP2050]  11.24 12.81 0 top
TP41  *  [TP2650]  112.71 122.67 180 bottom
TP42  *  [TP2650]  110.04 121.53 180 bottom
TP43  *  [TP2650]  111.32 121.65 180 bottom
TP44  *PAD  [TP2050]  111.57 120.38 180 bottom
TP45  *PAD  [TP2050]  111.64 118.81 180 bottom
TP46  *  [TP2650]  108.27 118.5 180 bottom
TP47  *  [TP2650]  109.81 118.53 180 bottom
TP48  *PAD  [TP2050]  99.73 119.09 180 bottom
TP49  *PAD  [TP2050]  95.69 100.32 180 bottom
TP50  *PAD  [TP2050]  96.96 100.32 180 bottom
TP51  *PAD  [TP2050]  121.98 88.4 180 bottom
TP52  *  [TP2650]  123.28 87.74 180 bottom
TP53  *PAD_NC  [TP2050]  22.06 82.28 180 bottom
TP54  *PAD_NC  [TP2050]  23.63 82.28 180 bottom
TP55  *PAD_NC  [TP2050]  86.8 82.28 90 bottom
TP56  *PAD_NC  [TP2050]  89.11 81.39 180 bottom
TP57  *PAD_NC  [TP2050]  82.36 78.6 180 bottom
TP58  *PAD  [TP2050]  60.64 53.2 180 bottom
TP59  *TP  [TP2050]  74.48 52.56 180 bottom
TP60  *TP  [TP2050]  72.63 52.59 180 bottom
TP61  *PAD_NC  [TP2050]  109.54 47.99 180 bottom
TP62  *TP  [TP2050]  74.61 46.47 180 bottom
TP63  *PAD_NC  [TP2050]  150.3 41.77 180 bottom
TP64  *PAD_NC  [TP2675]  89.37 35.6 180 bottom
TP65  *PAD_NC  [TP2675]  90.74 36.94 180 bottom
TP66  *PAD_NC  [TP2050]  95.85 36.41 180 bottom
TP67  *PAD_NC  [TP2050]  97.12 36.41 180 bottom
TP68  *PAD_NC  [TP2050]  98.39 36.41 180 bottom
TP69  *PAD_NC  [TP2050]  99.66 36.41 180 bottom
TP70  *PAD_NC  [TP2050]  103.21 36.44 90 bottom
TP71  *  [TP2675]  161 35.19 270 bottom
TP72  *PAD_NC  [TP2050]  96.66 34.89 180 bottom
TP73  *PAD_NC  [TP2050]  102.8 34.66 90 bottom
TP74  *  [TP2675]  164.65 34.53 180 bottom
TP75  *  [TP2675]  160.26 33.41 270 bottom
TP76  *  [TP2675]  158.38 33.74 0 top
TP77  *  [TP2675]  162.62 33.51 270 bottom
TP79  *PAD_NC  [TP2050]  195.72 28.51 180 bottom
TP80  *PAD_NC  [TP2050]  195.72 29.78 180 bottom
TP81  *  [TP2675]  163 29.2 0 top
TP82  *  [TP2675]  167.45 32.12 0 top
TP86  *PAD  [TP2050]  10.35 20.18 180 bottom
U1  *EV@MX25L2006EM1I-12G  [SOIC8-6-1_27-PM25LV010A]  113.22 122.8 270 top
U2  RTL8111HSH-CG  [QFN32-4X4-4-33P-0_9H]  44.64 105.4 270 top
U3  EV@TC7SH08FU(F)  [SOT353-1-2_125-65-5P]  92.77 95.36 270 top
U4  G5250Q1T73U  [SOT23-2_38-95-3P]  15.3 84.06 180 top
U5  MID@DDR4_96P  [BGA96-MICRON-MT41J64M16JT-187EG]  40.13 83.71 270 top
U6  MID@DDR4_96P  [BGA96-MICRON-MT41J64M16JT-187EG]  40.13 72.33 270 top
U7  USB30_ESD_AZ1065-06F.R7G  [ESD10-4_1X2-8-11P]  17.97 55.49 90 top
U8  *74AVC1T45FZ4-7  [DFN6-1_4X1-5]  119.44 50.02 90 top
U9  MID@DDR4_96P  [BGA96-MICRON-MT41J64M16JT-187EG]  40.13 48.73 270 top
U10  TPC@SLGC55544VTR  [QFN16-3X3-5-17P-TPS2546RTER]  20.13 48.63 0 top
U11  *HDT@SN74LVC2G07DCKR  [SC70-2_1-65-6P-0_95H]  117.16 38.54 270 top
U12  MID@DDR4_96P  [BGA96-MICRON-MT41J64M16JT-187EG]  40.13 37.35 270 top
U13  USB30_ESD_AZ1065-06F.R7G  [ESD10-4_1X2-8-11P]  18.73 34.78 90 top
U14  *TC7SH08FU(F)  [SOT353-1-2_125-65-5P]  102.42 24.5 0 top
U15  IT8987E/BX  [LQFP128-16X16-4-1_6H]  173.42 21.96 270 top
U16  TPM@NPCT750AADYX  [QFN32-5X5-5-33P-0_85H]  125.69 21.35 90 top
U17  GS@LIS3DHTR  [LGA16-3X3-5]  65.16 18.2 0 top
U18  SN75LVCP601RTJR  [PWQFN20-4X4-5-26P-0_8H]  210.25 16.37 180 top
U19  TPC@RTS5441E-GR  [QFN24-4X4-5-25P-RT9921CGQV]  18.86 15.61 270 top
U20  *MS@SY6288C20AAC  [SOT23-2_85-95-5P]  186.78 15.1 0 top
U21  *SSD@TC7SH08FU(F)  [SOT353-1-2_125-65-5P]  19.62 7.73 180 top
U22  EV@Si51214-A1EAGM  [DFN6-1_4X1_2-4]  104.58 120.64 90 bottom
U23  EV@TC7SH08FU(F)  [SOT353-1-2_125-65-5P]  60.89 119.54 0 bottom
U24  NS892407  [TRF-N1010G-25P]  32.4 107.58 180 bottom
U25  EV@R19M-P18-50  [BGA769-AMD-FT3]  112 103.72 180 bottom
U26  SY6288C20AAC  [SOT23-2_85-95-5P]  66.48 92.44 90 bottom
U27  *AZ1045-04F.R7G  [ESD10-2_5X1-5-9P-AZ1143]  14.29 78.09 270 bottom
U28  PS8409AQFN48GTR2-A2  [QFN48-6X6-4-49P-PS8409]  20.53 78.07 180 bottom
U29  *AZ1045-04F.R7G  [ESD10-2_5X1-5-9P-AZ1143]  14.29 74.87 90 bottom
U30  CPU_AMD_FP6  [BGA1140-AMD-FP5]  90.51 56.99 270 bottom
U31  G524B2T11U  [SOT23-5-2_8-95-5P-G708]  19.49 44.18 180 bottom
U32  G781-1P8  [MSOP8-4_9-65-G547]  18.73 33.9 0 bottom
U33  *74LVC1G17GW  [SOT353-1-2_125-65-5P]  102.93 32.63 180 bottom
U34  MX25U12835FM2I-10G  [SOIC8-7_9-1_27-2_16H]  162.11 30.09 270 bottom
U35  ALC256-CG  [QFN48-6X6-4-49P-ALC280]  203.13 26.66 90 bottom
U36  TPC@G518A1TO1U  [SOT23-2_8-95-5P-G518A1TO1U]  16.44 24.12 180 bottom
U37  *W25X10CLSNIG  [SOIC8-6-1_27-PM25LV010A]  161.35 22.97 0 bottom
U38  G524B2T11U  [SOT23-5-2_8-95-5P-G708]  211.11 21.7 90 bottom
U39  TPC@PTN36001  [QFN12-1_25X2_1-4]  16.57 15.73 180 bottom
VRAM1  EV@GDDR5  [BGA170-MICRON-MT51J256M32HF]  140.38 110.98 180 bottom
VRAM2  EV@GDDR5  [BGA170-MICRON-MT51J256M32HF]  140.38 88.59 0 bottom
Y1  25MHZ/30ppm  [XTL-2_05X1_65-1_4X1_1-0_6H]  44.77 113.12 180 top
Y2  EV@27MHZ/10ppm  [XTL-3_2X2_5-2_2X1_6-0_9H]  104.07 124.45 0 bottom
Y3  32.768KHZ/20ppm  [XTL-3_2X1_5-2_5-SMT]  107.88 39.61 270 bottom
Y4  48MHZ/15ppm  [XTL-3_2X2_5-2_2X1_8-4P]  107 34.28 180 bottom

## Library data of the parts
C1 C2 C9 C21 C66 C67 C100 C103 C117 C130 C138 C150 C157 C191 C198 C225 C238 C240 C279 C317 C324 C329 C332 C335 C337 C339 C343 C344 C353 C366 C367 C369 C373 C379 C381 C394 C400 C401 C409 C410 C414 C416 C417 C420-C422 C424-C426 C428-C431 C441-C443 C450 C455-C458 C478 C484 C486 C487 C490-C493 C495 C496 C501 C502 C528 C535 C536 C539-C541 C545 C556-C558 C571 C581 C582 C615 C620 C621 C626-C631 C634-C641 C643 C644 C646 C651-C653 C656-C660 C665 C667-C670 C674 C677 C679 C680 C682 C698 C699 C701 C709-C711 C714 EC3 PC14 PC15 PC17 PC18 PC24 PC30 PC38-PC41 PC50-PC59 PC62-PC71 PC73 PC74 PC79 PC80 PC128 PC146 PC151 PC153 PC157-PC167 PC170 PC172 PC175-PC180 PC182 PC183 PC193-PC196 PC203 PC206 PC207 PC209 PC210 PC214 PC216 PC220 PC221 PC223 PC225 PC229-PC233 PC236-PC244 PC248-PC256 PC259 = CAP NON-POL_BGM
C3-C8 C10-C20 C22-C49 C51-C58 C60-C65 C68-C79 C82-C88 C90 C93 C94 C96-C99 C101 C102 C104-C108 C110 C111 C114-C116 C118-C124 C126-C129 C131-C137 C139-C149 C151-C156 C158-C190 C192-C197 C199-C224 C226-C237 C239 C241-C278 C280-C316 C318-C323 C325-C328 C330 C331 C333 C334 C336 C338 C340-C342 C345-C352 C354-C365 C368 C370-C372 C374-C378 C380 C382-C393 C395-C399 C402-C408 C411-C413 C415 C418 C419 C423 C427 C432-C440 C444-C449 C451-C454 C459-C477 C479-C483 C485 C488 C489 C494 C497-C500 C504-C519 C529 C531-C534 C537 C538 C542-C544 C546-C555 C559-C566 C568-C570 C572-C580 C583-C614 C616-C619 C622-C625 C632 C633 C642 C645 C647-C650 C654 C655 C661-C664 C666 C671-C673 C675 C676 C678 C681 C683-C697 C700 C702-C708 C712 C713 PC1-PC11 PC13 PC16 PC19-PC23 PC25-PC29 PC31 PC32 PC34-PC37 PC43-PC49 PC60 PC61 PC75-PC78 PC81-PC127 PC129-PC145 PC147-PC150 PC152 PC154 PC155 PC168 PC169 PC171 PC173 PC184-PC192 PC197-PC199 PC201 PC202 PC205 PC208 PC211 PC212 PC215 PC217-PC219 PC222 PC224 PC226-PC228 PC234 PC245 PC246 PC257 PC258 PC260-PC308 = CAP_NON-POL_BGM
C50 C59 C80 C81 C91 C92 C95 C109 C112 C113 C125 C503 C530 C567 = C
C89 = CAPACITOR POL_4
CN1 = HEADER_4P_50208-00401-V02_BGM
CN2 = FFCFPC_40P_BGM
CN3 = RJ45_8P_4fix_V3_BGM
CN4 = HDMI_19P_10444-19001_BGM
CN5 = DDR4_DIMM_260P_BGM
CN6 CN9 = HEADER 4_0
CN7 = Header_20P_2R_WOFIXP_BGM
CN8 = FFCFPC_40P_BGM_0
CN10 CN16 = FFCFPC_28P_BGM
CN11 = NGFF_79P_EKEY_NAME_BGM
CN12 CN13 = FFCFPC_8P_BGM
CN14 CN18 = FFCFPC_4P_BGM
CN15 = USB3_1_24P_8F_V5_BGM
CN17 = FFCFPC_18P_BGM
CN19 = NGFF_79P_MKEY_NAME_BGM
CN20 = Header_2P_BGM
D1-D3 D5 D10-D23 D33 = Schottky_DIODE_BGM
D4 D28-D32 = DIODE_BGM
D6 D24 D35 D36 D38 = Varistor_BGM
D7 = DIODE SCHOTTKY_1
D8 D25 = 1N4148
D9 D26 D27 D34 D37 EC1 EC2 RV8 RV9 = TVS_DIODE_BGM
FAN1 = Header_4P_BGM
FB1 PL1-PL16 = INDUCTOR_BGM
HD1 = FFCFPC_12P_V1_BGM
HE1 HE2 = HALL_IC_3P_BGM
HOLE1 HOLE3-HOLE6 HOLE8-HOLE12 HOLE15 HOLE16 HOLE20-HOLE22 = 3x2_1.1: tolerance: MBZ8P003010
HOLE2 HOLE14 HOLE18 HOLE19 HOLE23 = 3x2_0.1: tolerance: *
HOLE13 HOLE17 = 3x2_1.1: tolerance: MBZAU001010
J1 = OPEN
L1-L14 = BEAD_BGM
PC12 PC33 PC42 PC72 PC156 PC174 PC181 PC200 PC204 PC213 PC235 PC247 = CAP_POL_BGM
PD1 PD3 PD4 = ZENER_DIODE_BGM
PD2 = BAT54C_BGM
PJ3 PJ6-PJ8 PJ15 PJ17 PR1 PR5 PR7 PR8 PR10 PR18 PR21 PR22 PR24 PR29 PR30 PR32 PR36-PR38 PR40-PR42 PR46 PR51-PR54 PR63 PR71 PR72 PR76 PR79 PR81 PR83 PR88 PR90 PR93 PR94 PR99 PR102-PR104 PR109 PR111 PR114 PR116 PR117 PR119 PR120 PR122 PR132 PR134 PR135 PR137 PR140 PR142 PR155 PR158 PR159 PR162 PR163 PR167 PR168 PR174 PR179 PR184 PR186 PR188 PR192 PR196 PR197 PR202 PR208 PR209 PR216 PR218 PR221 PR229 PR230 PR233 PR236 PR247 PR248 PR251 PR253 PR265 PR271 PR272 PR284 PR288 PR290 PR295 PR297-PR300 PR302 PR306 PR309 PR310 PR315-PR318 PR322-PR325 PR327 PR329 PR330 PR335 PR337 PR342 PR343 PR348 PR351 = SHORTPAD_V01_BGM
PJ11 = DCJACK_30706-00042-001_BGM
PJ18 = HEADER_8P_2F_BGM
PQ1 PQ3 PQ9 PQ31 PQ34 = MOS-N_8P_BGM
PQ2 PQ4-PQ7 PQ10-PQ13 PQ15 PQ18-PQ20 PQ22-PQ25 PQ28 PQ29 Q4 Q5 Q9 Q10 Q13 Q15-Q18 Q22 Q24-Q26 Q28 Q32 Q33 Q35 Q38 = MOS-N_3P_ESD_BGM
PQ8 PQ26 Q42 Q43 = MOS-N_3P_ESD_V3_BGM
PQ14 = MOS-N-Dual_9P_BGM
PQ16 PQ17 PQ32 PQ33 = MOS-N-Dual_10P_BGM
PQ21 Q2 Q40 = DTC144EU_BGM
PQ27 Q1 Q21 Q23 Q27 Q34 Q41 = MOS-P_3P_BGM
PQ30 PQ35 PQ36 = MOS-N_8P_V3_BGM
PR2-PR4 PR6 PR9 PR11-PR15 PR17 PR19 PR20 PR23 PR25-PR28 PR31 PR33-PR35 PR39 PR43-PR45 PR47-PR50 PR55-PR62 PR64-PR70 PR73-PR75 PR77 PR78 PR80 PR82 PR84-PR87 PR89 PR91 PR92 PR95-PR98 PR100 PR101 PR105-PR108 PR110 PR112 PR113 PR115 PR118 PR121 PR125 PR126 PR128-PR130 PR133 PR138 PR139 PR141 PR143 PR144 PR146 PR147 PR149-PR154 PR156 PR157 PR160 PR161 PR164-PR166 PR169-PR173 PR175-PR178 PR180-PR183 PR185 PR187 PR189-PR191 PR193-PR195 PR198 PR199 PR203-PR207 PR210-PR215 PR217 PR219 PR220 PR222-PR228 PR231 PR232 PR237-PR246 PR249 PR250 PR252 PR254-PR264 PR266-PR270 PR273-PR281 PR285-PR287 PR289 PR291-PR294 PR296 PR301 PR303-PR305 PR307 PR308 PR311-PR314 PR319-PR321 PR326 PR328 PR331-PR334 PR336 PR338-PR341 PR345-PR347 PR349 PR350 PR352 R2 R6 R9 R15 R17 R21 R25 R28 R32-R34 R40 R43 R52-R58 R60-R65 R67 R69-R71 R74-R77 R79-R81 R83 R84 R91-R94 R96-R100 R103-R119 R121-R124 R126 R128-R136 R139-R141 R143-R163 R165-R181 R183-R188 R190-R221 R223 R225 R229 R231-R235 R237-R239 R244-R257 R259-R262 R265-R267 R269-R271 R273-R276 R278 R281-R284 R286 R287 R289 R290 R293 R296 R298 R299 R301-R315 R317-R327 R329-R334 R336-R339 R341-R343 R345-R349 R352-R358 R363-R368 R370-R383 R385-R416 R418-R421 R423 R424 R426 R428-R431 R433 R435 R439 R446-R448 R455 R456 R465-R467 R474 R480 R489 R496 R498-R517 R519 R522-R525 R527 R529-R532 R535-R538 R541 R543 R546 R549-R552 R556-R559 R562-R565 R568-R585 R587 R588 R590 R592 R593 R595 R597-R617 R619-R640 R642-R644 R646-R664 R667-R687 R689 R690 R692-R699 R701-R710 R712-R719 R721-R732 R734-R738 R747 = RES_BGM
PR16 PR344 R89 R494 = R_Current_SEN_BGM
PR123 PR124 PR200 PR201 PR234 PR235 PR282 PR283 = Thermistor_BGM
PR127 PR131 PR136 PR145 PR148 = SRES_BGM
PU1 = TPS51486XRJER_18P_BGM
PU2 PU7 = JW5213DFND_8P_BGM
PU3 PU8 = RT3662ACGQW_BGM
PU4 PU5 = AOZ1331ADI_14P_BGM
PU6 = JW5222RSOTB#TRPBF_6P_V1_BGM
PU9 = UP8801SSW8_8P_BGM
PU10 PU11 = G5335QT2U_BGM
PU12 = TMP708_BGM
PU13 = RT6256BGQUF_12P_BGM
PU14 = BQ24780SRUYR_BGM
PU15 = RT6258CGQUF_12P_BGM
Q3 Q6 Q7 Q19 Q20 = MOS-N_Dual_6P_ESD_BGM
Q8 Q11 Q12 Q30 = NPN_V2_BGM
Q14 = NPN_0
Q29 = 2N7002DW
Q31 Q39 = 2N7002
Q36 = NPN_BGM
Q44 = MOS-N_3P_ESD_BGM: tolerance: BAN70020007
R1 R3-R5 R7 R8 R10-R14 R16 R18-R20 R22-R24 R26 R27 R29-R31 R35-R39 R41 R42 R44 R45 R95 R189 R224 R226-R228 R230 R236 R241-R243 R272 R279 R294 R300 R436-R438 R440-R445 R450-R454 R458-R464 R468-R473 R476-R479 R482-R487 R490-R492 R520 R586 R589 R591 R594 R618 R641 R748 = RES_BGM_1
R46-R51 R125 R127 R457 R495 R497 R526 R528 R547 R548 R553-R555 = R_31
R59 R120 R518 R521 = R_40
R66 R72 = RES_BGM: tolerance: CS00004JA40
R68 R73 R78 = RES_BGM: tolerance: CS21001JE14
R82 R182 R240 R280 R288 R291 R295 R297 R344 R359-R362 R542 R544 R545 R665 R666 = RES_BGM: tolerance: CS00003J951
R85-R87 R138 R316 R350 R427 R449 R475 R534 R539 R540 = R_30
R88 R90 R101 R102 = R_22
R137 R142 R164 R222 R258 R263 R285 R351 R369 R384 R422 R425 R432 R434 R533 R560 R561 R566 R567 R691 R733 = RES_S_BGM
R264 R268 R277 R292 R328 R335 R340 R417 R493 R596 R688 R700 R711 R720 R739-R746 = RES_BGM: tolerance: CS00002JB38
R481 = R_23
R488 = RES_BGM: tolerance: CS41002JB20
R645 = SHORTPAD_BGM
RV1 RV2 RV5 RV6 = VARISTOR_BGM
RV3 RV7 = TPD4E02B04DQAR_BGM
SW1 = SW_6P_BGM
SW2 = SW_6P_R_BGM
SW3 = SW_4P_BGM
TP1 TP3-TP6 TP8 TP13-TP16 TP44 TP45 TP48-TP51 TP64 TP65 = PAD_0
TP2 TP7 TP9-TP12 TP18 TP20 TP25 TP28 TP30 TP33-TP37 TP39 TP41-TP43 TP46 TP47 TP52 TP58-TP60 TP62 TP71 TP74-TP77 TP81 TP82 TP86 = TP_BGM
TP17 TP19 TP21-TP24 TP27 TP53-TP57 TP61 TP63 TP66-TP70 TP72 TP73 TP79 TP80 = PAD_3
U1 = SST25LF080A_0
U2 = RTL8111HSH-CG_BGM
U3 U14 U21 U23 = Logic_AND_BGM
U4 = G5250Q1T73U_BGM
U5 U6 U9 U12 = DDR4_96P_BGM_0
U7 U13 = LXESEABAA6-046_0
U8 = G2129BAJ1U_8P_BGM_4
U10 = SLGC55544VTR_BGM
U11 = 74LVC2G07GW_BGM
U15 = IT8987E/CX_BGM_0
U16 = NPCT750AAAYX_32P_BGM
U17 = LIS3DHTR_BGM
U18 = SN75LVCP601RTJR_BGM
U19 = RTS5441E-GR_24P_BGM
U20 U26 = SY6288C20AAC_BGM
U22 = SI51214
U24 = NS680016_0
U25 = BAFFIN
U27 U29 = AZ1045-04F_BGM
U28 = PS8209AQFN48GTR2-A2_48P_BGM
U30 = CPU_AMD_FP6_1140P_BGM
U31 U38 = MAX8863_2
U32 = G781_BGM
U33 = 74LVC1G17GW_5P_BGM
U34 = W25Q64FWSSIG_BGM
U35 = ALC255-CG_BGM_0
U36 = G518A1TO1U_5P_BGM
U37 = W25X10CLSNIG_BGM
U39 = 53398-0410_2
VRAM1 VRAM2 = 170BALL_GDDR5_1
Y1 Y2 Y4 = CRYSTAL_4P_BGM
Y3 = CRYSTAL_2P_BGM

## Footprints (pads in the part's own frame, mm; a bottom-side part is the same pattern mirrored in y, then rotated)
2D-BARCODE-8X8-S
  round 0.991 smd: 1(7,-4)
132F18-100000-A2-R-18P-L
  rect 0.305x0.838 smd: 1(-4.25,3.175) 2(-3.75,3.175) 3(-3.25,3.175) 4(-2.75,3.175) 5(-2.25,3.175) 6(-1.75,3.175) 7(-1.25,3.175) 8(-0.75,3.175) 9(-0.25,3.175) 10(0.25,3.175) 11(0.75,3.175) 12(1.25,3.175) 13(1.75,3.175) 14(2.25,3.175) 15(2.75,3.175) 16(3.25,3.175) 17(3.75,3.175) 18(4.25,3.175)
  rect 0.787x2.007 smd: 19(-5.95,0) 20(5.95,0)
50208-00401-V02-4P-L
  rect 0.508x0.991 smd: 1(-1.2,1.95) 2(-0.4,1.95) 3(0.4,1.95) 4(1.2,1.95)
  rect 1.194x1.702 smd: 5(-2.5,0) 6(2.5,0)
50281-00201-001-2P-L
  rect 0.787x2.007 smd: 1(-0.625,4.05) 2(0.625,4.05)
  rect 2.007x2.489 smd: 3(-2.825,0) 4(2.825,0)
50505-00401-V01-4P-L
  rect 0.61x1.295 smd: 1(-1.5,3.25) 2(-0.5,3.25) 3(0.5,3.25) 4(1.5,3.25)
  rect 0.991x2.007 smd: 5(-4.1,0) 6(4.1,0)
50584-0280N-V02-28P-L
  rect 0.61x1.092 smd: 1(-13.5,2.05) 2(-12.5,2.05) 3(-11.5,2.05) 4(-10.5,2.05) 5(-9.5,2.05) 6(-8.5,2.05) 7(-7.5,2.05) 8(-6.5,2.05) 9(-5.5,2.05) 10(-4.5,2.05) 11(-3.5,2.05) 12(-2.5,2.05) 13(-1.5,2.05) 14(-0.5,2.05) 15(0.5,2.05) 16(1.5,2.05) 17(2.5,2.05) 18(3.5,2.05) 19(4.5,2.05) 20(5.5,2.05) 21(6.5,2.05) 22(7.5,2.05) 23(8.5,2.05) 24(9.5,2.05) 25(10.5,2.05) 26(11.5,2.05) 27(12.5,2.05) 28(13.5,2.05)
  rect 2.159x2.997 smd: 29(-15.975,0) 30(15.975,0)
51325-00401-001-4P-L
  rect 0.61x1.549 smd: 1(-1.5,3.875) 2(-0.5,3.875) 3(0.5,3.875) 4(1.5,3.875)
  rect 1.194x1.803 smd: 5(-2.8,0) 6(2.8,0)
51625-01201-001-12P-L
  rect 0.305x0.838 smd: 1(-2.75,3.555) 2(-2.25,3.555) 3(-1.75,3.555) 4(-1.25,3.555) 5(-0.75,3.555) 6(-0.25,3.555) 7(0.25,3.555) 8(0.75,3.555) 9(1.25,3.555) 10(1.75,3.555) 11(2.25,3.555) 12(2.75,3.555)
  rect 0.991x1.448 smd: 13(-4.54,0) 14(4.54,0)
196047-08021-3-8P-L
  rect 0.305x1.295 smd: 1(-3.5,2.65) 2(-2.5,2.65) 3(-1.5,2.65) 4(-0.5,2.65) 5(0.5,2.65) 6(1.5,2.65) 7(2.5,2.65) 8(3.5,2.65)
  rect 1.803x1.397 smd: 9(-5.65,0) 10(5.65,0)
196241-08021-3-8P-L
  rect 0.305x1.295 smd: 1(-1.75,2.7) 2(-1.25,2.7) 3(-0.75,2.7) 4(-0.25,2.7) 5(0.25,2.7) 6(0.75,2.7) 7(1.25,2.7) 8(1.75,2.7)
  rect 1.854x1.397 smd: 9(-3.425,0) 10(3.425,0)
196538-40041-3-40P-L
  rect 0.305x0.838 smd: 1(-9.75,3.175) 2(-9.25,3.175) 3(-8.75,3.175) 4(-8.25,3.175) 5(-7.75,3.175) 6(-7.25,3.175) 7(-6.75,3.175) 8(-6.25,3.175) 9(-5.75,3.175) 10(-5.25,3.175) 11(-4.75,3.175) 12(-4.25,3.175) 13(-3.75,3.175) 14(-3.25,3.175) 15(-2.75,3.175) 16(-2.25,3.175) 17(-1.75,3.175) 18(-1.25,3.175) 19(-0.75,3.175) 20(-0.25,3.175) 21(0.25,3.175) 22(0.75,3.175) 23(1.25,3.175) 24(1.75,3.175) 25(2.25,3.175) 26(2.75,3.175) 27(3.25,3.175) 28(3.75,3.175) 29(4.25,3.175) 30(4.75,3.175) 31(5.25,3.175) 32(5.75,3.175) 33(6.25,3.175) 34(6.75,3.175) 35(7.25,3.175) 36(7.75,3.175) 37(8.25,3.175) 38(8.75,3.175) 39(9.25,3.175) 40(9.75,3.175)
  rect 0.787x2.007 smd: 41(-11.45,0) 42(11.45,0)
ASP-137098-05-20P-LDV
  rect 0.737x2.794 smd: 1(-5.715,-2.035) 2(-5.715,2.035) 3(-4.445,-2.035) 4(-4.445,2.035) 5(-3.175,-2.035) 6(-3.175,2.035) 7(-1.905,-2.035) 8(-1.905,2.035) 9(-0.635,-2.035) 10(-0.635,2.035) 11(0.635,-2.035) 12(0.635,2.035) 13(1.905,-2.035) 14(1.905,2.035) 15(3.175,-2.035) 16(3.175,2.035) 17(4.445,-2.035) 18(4.445,2.035) 19(5.715,-2.035) 20(5.715,2.035)
BGA96-MICRON-MT41J64M16JT-187EG
  round 0.356 smd: A1(-3.2,6) A2(-2.4,6) A3(-1.6,6) A7(1.6,6) A8(2.4,6) A9(3.2,6) B1(-3.2,5.2) B2(-2.4,5.2) B3(-1.6,5.2) B7(1.6,5.2) B8(2.4,5.2) B9(3.2,5.2) C1(-3.2,4.4) C2(-2.4,4.4) C3(-1.6,4.4) C7(1.6,4.4) C8(2.4,4.4) C9(3.2,4.4) D1(-3.2,3.6) D2(-2.4,3.6) D3(-1.6,3.6) D7(1.6,3.6) D8(2.4,3.6) D9(3.2,3.6) E1(-3.2,2.8) E2(-2.4,2.8) E3(-1.6,2.8) E7(1.6,2.8) E8(2.4,2.8) E9(3.2,2.8) F1(-3.2,2) F2(-2.4,2) F3(-1.6,2) F7(1.6,2) F8(2.4,2) F9(3.2,2) G1(-3.2,1.2) G2(-2.4,1.2) G3(-1.6,1.2) G7(1.6,1.2) G8(2.4,1.2) G9(3.2,1.2) H1(-3.2,0.4) H2(-2.4,0.4) H3(-1.6,0.4) H7(1.6,0.4) H8(2.4,0.4) H9(3.2,0.4) J1(-3.2,-0.4) J2(-2.4,-0.4) J3(-1.6,-0.4) J7(1.6,-0.4) J8(2.4,-0.4) J9(3.2,-0.4) K1(-3.2,-1.2) K2(-2.4,-1.2) K3(-1.6,-1.2) K7(1.6,-1.2) K8(2.4,-1.2) K9(3.2,-1.2) L1(-3.2,-2) L2(-2.4,-2) L3(-1.6,-2) L7(1.6,-2) L8(2.4,-2) L9(3.2,-2) M1(-3.2,-2.8) M2(-2.4,-2.8) M3(-1.6,-2.8) M7(1.6,-2.8) M8(2.4,-2.8) M9(3.2,-2.8) N1(-3.2,-3.6) N2(-2.4,-3.6) N3(-1.6,-3.6) N7(1.6,-3.6) N8(2.4,-3.6) N9(3.2,-3.6) P1(-3.2,-4.4) P2(-2.4,-4.4) P3(-1.6,-4.4) P7(1.6,-4.4) P8(2.4,-4.4) P9(3.2,-4.4) R1(-3.2,-5.2) R2(-2.4,-5.2) R3(-1.6,-5.2) R7(1.6,-5.2) R8(2.4,-5.2) R9(3.2,-5.2) T1(-3.2,-6) T2(-2.4,-6) T3(-1.6,-6) T7(1.6,-6) T8(2.4,-6) T9(3.2,-6)
BGA170-MICRON-MT51J256M32HF
  round 0.356 smd: A1(-6.4,-5.2) A2(-6.4,-4.4) A3(-6.4,-3.6) A4(-6.4,-2.8) A5(-6.4,-2) A10(-6.4,2) A11(-6.4,2.8) A12(-6.4,3.6) A13(-6.4,4.4) A14(-6.4,5.2) B1(-5.6,-5.2) B2(-5.6,-4.4) B3(-5.6,-3.6) B4(-5.6,-2.8) B5(-5.6,-2) B10(-5.6,2) B11(-5.6,2.8) B12(-5.6,3.6) B13(-5.6,4.4) B14(-5.6,5.2) C1(-4.8,-5.2) C2(-4.8,-4.4) C3(-4.8,-3.6) C4(-4.8,-2.8) C5(-4.8,-2) C10(-4.8,2) C11(-4.8,2.8) C12(-4.8,3.6) C13(-4.8,4.4) C14(-4.8,5.2) D1(-4,-5.2) D2(-4,-4.4) D3(-4,-3.6) D4(-4,-2.8) D5(-4,-2) D10(-4,2) D11(-4,2.8) D12(-4,3.6) D13(-4,4.4) D14(-4,5.2) E1(-3.2,-5.2) E2(-3.2,-4.4) E3(-3.2,-3.6) E4(-3.2,-2.8) E5(-3.2,-2) E10(-3.2,2) E11(-3.2,2.8) E12(-3.2,3.6) E13(-3.2,4.4) E14(-3.2,5.2) F1(-2.4,-5.2) F2(-2.4,-4.4) F3(-2.4,-3.6) F4(-2.4,-2.8) F5(-2.4,-2) F10(-2.4,2) F11(-2.4,2.8) F12(-2.4,3.6) F13(-2.4,4.4) F14(-2.4,5.2) G1(-1.6,-5.2) G2(-1.6,-4.4) G3(-1.6,-3.6) G4(-1.6,-2.8) G5(-1.6,-2) G10(-1.6,2) G11(-1.6,2.8) G12(-1.6,3.6) G13(-1.6,4.4) G14(-1.6,5.2) H1(-0.8,-5.2) H2(-0.8,-4.4) H3(-0.8,-3.6) H4(-0.8,-2.8) H5(-0.8,-2) H10(-0.8,2) H11(-0.8,2.8) H12(-0.8,3.6) H13(-0.8,4.4) H14(-0.8,5.2) J1(0,-5.2) J2(0,-4.4) J3(0,-3.6) J4(0,-2.8) J5(0,-2) J10(0,2) J11(0,2.8) J12(0,3.6) J13(0,4.4) J14(0,5.2) K1(0.8,-5.2) K2(0.8,-4.4) K3(0.8,-3.6) K4(0.8,-2.8) K5(0.8,-2) K10(0.8,2) K11(0.8,2.8) K12(0.8,3.6) K13(0.8,4.4) K14(0.8,5.2) L1(1.6,-5.2) L2(1.6,-4.4) L3(1.6,-3.6) L4(1.6,-2.8) L5(1.6,-2) L10(1.6,2) L11(1.6,2.8) L12(1.6,3.6) L13(1.6,4.4) L14(1.6,5.2) M1(2.4,-5.2) M2(2.4,-4.4) M3(2.4,-3.6) M4(2.4,-2.8) M5(2.4,-2) M10(2.4,2) M11(2.4,2.8) M12(2.4,3.6) M13(2.4,4.4) M14(2.4,5.2) N1(3.2,-5.2) N2(3.2,-4.4) N3(3.2,-3.6) N4(3.2,-2.8) N5(3.2,-2) N10(3.2,2) N11(3.2,2.8) N12(3.2,3.6) N13(3.2,4.4) N14(3.2,5.2) P1(4,-5.2) P2(4,-4.4) P3(4,-3.6) P4(4,-2.8) P5(4,-2) P10(4,2) P11(4,2.8) P12(4,3.6) P13(4,4.4) P14(4,5.2) R1(4.8,-5.2) R2(4.8,-4.4) R3(4.8,-3.6) R4(4.8,-2.8) R5(4.8,-2) R10(4.8,2) R11(4.8,2.8) R12(4.8,3.6) R13(4.8,4.4) R14(4.8,5.2) T1(5.6,-5.2) T2(5.6,-4.4) T3(5.6,-3.6) T4(5.6,-2.8) T5(5.6,-2) T10(5.6,2) T11(5.6,2.8) T12(5.6,3.6) T13(5.6,4.4) T14(5.6,5.2) U1(6.4,-5.2) U2(6.4,-4.4) U3(6.4,-3.6) U4(6.4,-2.8) U5(6.4,-2) U10(6.4,2) U11(6.4,2.8) U12(6.4,3.6) U13(6.4,4.4) U14(6.4,5.2)
BGA769-AMD-FT3
  round 0.4 smd: A2(-11.3,-10.7) A3(-11.3,-9.95) A39(-11.3,9.95) A40(-11.3,10.7) AA4(0,-9.2) AA5(0,-8.4) AA7(0,-7.6) AA8(0,-6.8) AA10(0,-6) AA11(0,-5) AA13(0,-4) AA15(0,-3) AA17(0,-2) AA19(0,-1) AA21(0,0) AA23(0,1) AA25(0,2) AA27(0,3) AA29(0,4) AA31(0,5) AA32(0,6) AA34(0,6.8) AA35(0,7.6) AA37(0,8.4) AA38(0,9.2) AC4(1.1,-9.2) AC5(1.1,-8.4) AC7(1.1,-7.6) AC8(1.1,-6.8) AC10(1.1,-6) AC11(1,-5) AC13(1,-4) AC15(1,-3) AC17(1,-2) AC19(1,-1) AC21(1,0) AC23(1,1) AC25(1,2) AC27(1,3) AC29(1,4) AC31(1,5) AC32(1.1,6) AC34(1.1,6.8) AC35(1.1,7.6) AC37(1.1,8.4) AC38(1.1,9.2) AE4(2.2,-9.2) AE5(2.2,-8.4) AE7(2.2,-7.6) AE8(2.2,-6.8) AE10(2.2,-6) AE11(2,-5) AE13(2,-4) AE15(2,-3) AE17(2,-2) AE19(2,-1) AE21(2,0) AE23(2,1) AE25(2,2) AE27(2,3) AE29(2,4) AE31(2,5) AE32(2.2,6) AE34(2.2,6.8) AE35(2.2,7.6) AE37(2.2,8.4) AE38(2.2,9.2) AG4(3.3,-9.2) AG5(3.3,-8.4) AG7(3.3,-7.6) AG8(3.3,-6.8) AG10(3.3,-6) AG11(3,-5) AG13(3,-4) AG15(3,-3) AG17(3,-2) AG19(3,-1) AG21(3,0) AG23(3,1) AG25(3,2) AG27(3,3) AG29(3,4) AG31(3,5) AG32(3.3,6) AG34(3.3,6.8) AG35(3.3,7.6) AG37(3.3,8.4) AG38(3.3,9.2) AJ4(4.4,-9.2) AJ5(4.4,-8.4) AJ7(4.4,-7.6) AJ8(4.4,-6.8) AJ10(4.4,-6) AJ11(4,-5) AJ13(4,-4) AJ15(4,-3) AJ17(4,-2) AJ19(4,-1) AJ21(4,0) AJ23(4,1) AJ25(4,2) AJ27(4,3) AJ29(4,4) AJ31(4,5) AJ32(4.4,6) AJ34(4.4,6.8) AJ35(4.4,7.6) AJ37(4.4,8.4) AJ38(4.4,9.2) AL4(5.5,-9.2) AL5(5.5,-8.4) AL7(5.5,-7.6) AL8(5.5,-6.8) AL10(5.5,-6) AL11(5,-5) AL13(5,-4) AL15(5,-3) AL17(5,-2) AL19(5,-1) AL21(5,0) AL23(5,1) AL25(5,2) AL27(5,3) AL29(5,4) AL31(5,5) AL32(5.5,6) AL34(5.5,6.8) AL35(5.5,7.6) AL37(5.5,8.4) AL38(5.5,9.2) AM11(6,-5.5) AM13(6,-4.4) AM15(6,-3.3) AM17(6,-2.2) AM19(6,-1.1) AM21(6,0) AM23(6,1.1) AM25(6,2.2) AM27(6,3.3) AM29(6,4.4) AM31(6,5.5) AN4(6.6,-9.2) AN5(6.6,-8.4) AN7(6.6,-7.6) AN8(6.6,-6.8) AN34(6.6,6.8) AN35(6.6,7.6) AN37(6.6,8.4) AN38(6.6,9.2) AP11(6.8,-5.5) AP13(6.8,-4.4) AP15(6.8,-3.3) AP17(6.8,-2.2) AP19(6.8,-1.1) AP21(6.8,0) AP23(6.8,1.1) AP25(6.8,2.2) AP27(6.8,3.3) AP29(6.8,4.4) AP31(6.8,5.5) AR4(7.7,-9.2) AR5(7.7,-8.4) AR7(7.7,-7.6) AR11(7.6,-5.5) AR13(7.6,-4.4) AR15(7.6,-3.3) AR17(7.6,-2.2) AR19(7.6,-1.1) AR21(7.6,0) AR23(7.6,1.1) AR25(7.6,2.2) AR27(7.6,3.3) AR29(7.6,4.4) AR31(7.6,5.5) AR35(7.7,7.6) AR37(7.7,8.4) AR38(7.7,9.2) AU4(8.8,-9.2) AU7(8.4,-7.7) AU9(8.4,-6.6) AU11(8.4,-5.5) AU13(8.4,-4.4) AU15(8.4,-3.3) AU17(8.4,-2.2) AU19(8.4,-1.1) AU21(8.4,0) AU23(8.4,1.1) AU25(8.4,2.2) AU27(8.4,3.3) AU29(8.4,4.4) AU31(8.4,5.5) AU33(8.4,6.6) AU35(8.4,7.7) AU38(8.8,9.2) AV7(9.2,-7.7) AV9(9.2,-6.6) AV11(9.2,-5.5) AV13(9.2,-4.4) AV15(9.2,-3.3) AV17(9.2,-2.2) AV19(9.2,-1.1) AV21(9.2,0) AV23(9.2,1.1) AV25(9.2,2.2) AV27(9.2,3.3) AV29(9.2,4.4) AV31(9.2,5.5) AV33(9.2,6.6) AV35(9.2,7.7) AW1(9.95,-11.3) AW41(9.95,11.3) AY1(10.7,-11.3) AY2(10.6,-10.6) AY40(10.6,10.6) AY41(10.7,11.3) B1(-10.7,-11.3) B2(-10.6,-10.6) B40(-10.6,10.6) B41(-10.7,11.3) BA2(11.3,-10.7) BA3(11.3,-9.95) BA39(11.3,9.95) BA40(11.3,10.7) C1(-9.95,-11.3) C41(-9.95,11.3) D7(-9.2,-7.7) D9(-9.2,-6.6) D11(-9.2,-5.5) D13(-9.2,-4.4) D15(-9.2,-3.3) D17(-9.2,-2.2) D19(-9.2,-1.1) D21(-9.2,0) D23(-9.2,1.1) D25(-9.2,2.2) D27(-9.2,3.3) D29(-9.2,4.4) D31(-9.2,5.5) D33(-9.2,6.6) D35(-9.2,7.7) E4(-8.8,-9.2) E7(-8.4,-7.7) E9(-8.4,-6.6) E11(-8.4,-5.5) E13(-8.4,-4.4) E15(-8.4,-3.3) E17(-8.4,-2.2) E19(-8.4,-1.1) E21(-8.4,0) E23(-8.4,1.1) E25(-8.4,2.2) E27(-8.4,3.3) E29(-8.4,4.4) E31(-8.4,5.5) E33(-8.4,6.6) E35(-8.4,7.7) E38(-8.8,9.2) G4(-7.7,-9.2) G5(-7.7,-8.4) G7(-7.7,-7.6) G11(-7.6,-5.5) G13(-7.6,-4.4) G15(-7.6,-3.3) G17(-7.6,-2.2) G19(-7.6,-1.1) G21(-7.6,0) G23(-7.6,1.1) G25(-7.6,2.2) G27(-7.6,3.3) G29(-7.6,4.4) G31(-7.6,5.5) G35(-7.7,7.6) G37(-7.7,8.4) G38(-7.7,9.2) H11(-6.8,-5.5) H13(-6.8,-4.4) H15(-6.8,-3.3) H17(-6.8,-2.2) H19(-6.8,-1.1) H21(-6.8,0) H23(-6.8,1.1) H25(-6.8,2.2) H27(-6.8,3.3) H29(-6.8,4.4) H31(-6.8,5.5) J4(-6.6,-9.2) J5(-6.6,-8.4) J7(-6.6,-7.6) J8(-6.6,-6.8) J34(-6.6,6.8) J35(-6.6,7.6) J37(-6.6,8.4) J38(-6.6,9.2) K11(-6,-5.5) K13(-6,-4.4) K15(-6,-3.3) K17(-6,-2.2) K19(-6,-1.1) K21(-6,0) K23(-6,1.1) K25(-6,2.2) K27(-6,3.3) K29(-6,4.4) K31(-6,5.5) L4(-5.5,-9.2) L5(-5.5,-8.4) L7(-5.5,-7.6) L8(-5.5,-6.8) L10(-5.5,-6) L11(-5,-5) L13(-5,-4) L15(-5,-3) L17(-5,-2) L19(-5,-1) L21(-5,0) L23(-5,1) L25(-5,2) L27(-5,3) L29(-5,4) L31(-5,5) L32(-5.5,6) L34(-5.5,6.8) L35(-5.5,7.6) L37(-5.5,8.4) L38(-5.5,9.2) N4(-4.4,-9.2) N5(-4.4,-8.4) N7(-4.4,-7.6) N8(-4.4,-6.8) N10(-4.4,-6) N11(-4,-5) N13(-4,-4) N15(-4,-3) N17(-4,-2) N19(-4,-1) N21(-4,0) N23(-4,1) N25(-4,2) N27(-4,3) N29(-4,4) N31(-4,5) N32(-4.4,6) N34(-4.4,6.8) N35(-4.4,7.6) N37(-4.4,8.4) N38(-4.4,9.2) R4(-3.3,-9.2) R5(-3.3,-8.4) R7(-3.3,-7.6) R8(-3.3,-6.8) R10(-3.3,-6) R11(-3,-5) R13(-3,-4) R15(-3,-3) R17(-3,-2) R19(-3,-1) R21(-3,0) R23(-3,1) R25(-3,2) R27(-3,3) R29(-3,4) R31(-3,5) R32(-3.3,6) R34(-3.3,6.8) R35(-3.3,7.6) R37(-3.3,8.4) R38(-3.3,9.2) U4(-2.2,-9.2) U5(-2.2,-8.4) U7(-2.2,-7.6) U8(-2.2,-6.8) U10(-2.2,-6) U11(-2,-5) U13(-2,-4) U15(-2,-3) U17(-2,-2) U19(-2,-1) U21(-2,0) U23(-2,1) U25(-2,2) U27(-2,3) U29(-2,4) U31(-2,5) U32(-2.2,6) U34(-2.2,6.8) U35(-2.2,7.6) U37(-2.2,8.4) U38(-2.2,9.2) W4(-1.1,-9.2) W5(-1.1,-8.4) W7(-1.1,-7.6) W8(-1.1,-6.8) W10(-1.1,-6) W11(-1,-5) W13(-1,-4) W15(-1,-3) W17(-1,-2) W19(-1,-1) W21(-1,0) W23(-1,1) W25(-1,2) W27(-1,3) W29(-1,4) W31(-1,5) W32(-1.1,6) W34(-1.1,6.8) W35(-1.1,7.6) W37(-1.1,8.4) W38(-1.1,9.2)
  round 0.3 smd: A4(-10.95,-9.35) A5(-11.3,-8.8) A6(-10.95,-8.25) A7(-11.3,-7.7) A8(-10.95,-7.15) A9(-11.3,-6.6) A10(-10.95,-6.05) A11(-11.3,-5.5) A12(-10.95,-4.95) A13(-11.3,-4.4) A14(-10.95,-3.85) A15(-11.3,-3.3) A16(-10.95,-2.75) A17(-11.3,-2.2) A18(-10.95,-1.65) A19(-11.3,-1.1) A20(-10.95,-0.55) A21(-11.3,0) A22(-10.95,0.55) A23(-11.3,1.1) A24(-10.95,1.65) A25(-11.3,2.2) A26(-10.95,2.75) A27(-11.3,3.3) A28(-10.95,3.85) A29(-11.3,4.4) A30(-10.95,4.95) A31(-11.3,5.5) A32(-10.95,6.05) A33(-11.3,6.6) A34(-10.95,7.15) A35(-11.3,7.7) A36(-10.95,8.25) A37(-11.3,8.8) A38(-10.95,9.35) AA1(0,-11.3) AA2(0,-10.6) AA3(0,-9.9) AA39(0,9.9) AA40(0,10.6) AA41(0,11.3) AB1(0.55,-10.95) AB2(0.55,-10.25) AB40(0.55,10.25) AB41(0.55,10.95) AC1(1.1,-11.3) AC2(1.1,-10.6) AC3(1.1,-9.9) AC39(1.1,9.9) AC40(1.1,10.6) AC41(1.1,11.3) AD1(1.65,-10.95) AD2(1.65,-10.25) AD40(1.65,10.25) AD41(1.65,10.95) AE1(2.2,-11.3) AE2(2.2,-10.6) AE3(2.2,-9.9) AE39(2.2,9.9) AE40(2.2,10.6) AE41(2.2,11.3) AF1(2.75,-10.95) AF2(2.75,-10.25) AF40(2.75,10.25) AF41(2.75,10.95) AG1(3.3,-11.3) AG2(3.3,-10.6) AG3(3.3,-9.9) AG39(3.3,9.9) AG40(3.3,10.6) AG41(3.3,11.3) AH1(3.85,-10.95) AH2(3.85,-10.25) AH40(3.85,10.25) AH41(3.85,10.95) AJ1(4.4,-11.3) AJ2(4.4,-10.6) AJ3(4.4,-9.9) AJ39(4.4,9.9) AJ40(4.4,10.6) AJ41(4.4,11.3) AK1(4.95,-10.95) AK2(4.95,-10.25) AK40(4.95,10.25) AK41(4.95,10.95) AL1(5.5,-11.3) AL2(5.5,-10.6) AL3(5.5,-9.9) AL39(5.5,9.9) AL40(5.5,10.6) AL41(5.5,11.3) AM1(6.05,-10.95) AM2(6.05,-10.25) AM40(6.05,10.25) AM41(6.05,10.95) AN1(6.6,-11.3) AN2(6.6,-10.6) AN3(6.6,-9.9) AN39(6.6,9.9) AN40(6.6,10.6) AN41(6.6,11.3) AP1(7.15,-10.95) AP2(7.15,-10.25) AP40(7.15,10.25) AP41(7.15,10.95) AR1(7.7,-11.3) AR2(7.7,-10.6) AR3(7.7,-9.9) AR39(7.7,9.9) AR40(7.7,10.6) AR41(7.7,11.3) AT1(8.25,-10.95) AT2(8.25,-10.25) AT40(8.25,10.25) AT41(8.25,10.95) AU1(8.8,-11.3) AU2(8.8,-10.6) AU3(8.8,-9.9) AU39(8.8,9.9) AU40(8.8,10.6) AU41(8.8,11.3) AV1(9.35,-10.95) AV2(9.35,-10.25) AV40(9.35,10.25) AV41(9.35,10.95) AW2(9.9,-10.6) AW3(9.9,-9.9) AW5(9.9,-8.8) AW7(9.9,-7.7) AW9(9.9,-6.6) AW11(9.9,-5.5) AW13(9.9,-4.4) AW15(9.9,-3.3) AW17(9.9,-2.2) AW19(9.9,-1.1) AW21(9.9,0) AW23(9.9,1.1) AW25(9.9,2.2) AW27(9.9,3.3) AW29(9.9,4.4) AW31(9.9,5.5) AW33(9.9,6.6) AW35(9.9,7.7) AW37(9.9,8.8) AW39(9.9,9.9) AW40(9.9,10.6) AY3(10.6,-9.9) AY4(10.25,-9.35) AY5(10.6,-8.8) AY6(10.25,-8.25) AY7(10.6,-7.7) AY8(10.25,-7.15) AY9(10.6,-6.6) AY10(10.25,-6.05) AY11(10.6,-5.5) AY12(10.25,-4.95) AY13(10.6,-4.4) AY14(10.25,-3.85) AY15(10.6,-3.3) AY16(10.25,-2.75) AY17(10.6,-2.2) AY18(10.25,-1.65) AY19(10.6,-1.1) AY20(10.25,-0.55) AY21(10.6,0) AY22(10.25,0.55) AY23(10.6,1.1) AY24(10.25,1.65) AY25(10.6,2.2) AY26(10.25,2.75) AY27(10.6,3.3) AY28(10.25,3.85) AY29(10.6,4.4) AY30(10.25,4.95) AY31(10.6,5.5) AY32(10.25,6.05) AY33(10.6,6.6) AY34(10.25,7.15) AY35(10.6,7.7) AY36(10.25,8.25) AY37(10.6,8.8) AY38(10.25,9.35) AY39(10.6,9.9) B3(-10.6,-9.9) B4(-10.25,-9.35) B5(-10.6,-8.8) B6(-10.25,-8.25) B7(-10.6,-7.7) B8(-10.25,-7.15) B9(-10.6,-6.6) B10(-10.25,-6.05) B11(-10.6,-5.5) B12(-10.25,-4.95) B13(-10.6,-4.4) B14(-10.25,-3.85) B15(-10.6,-3.3) B16(-10.25,-2.75) B17(-10.6,-2.2) B18(-10.25,-1.65) B19(-10.6,-1.1) B20(-10.25,-0.55) B21(-10.6,0) B22(-10.25,0.55) B23(-10.6,1.1) B24(-10.25,1.65) B25(-10.6,2.2) B26(-10.25,2.75) B27(-10.6,3.3) B28(-10.25,3.85) B29(-10.6,4.4) B30(-10.25,4.95) B31(-10.6,5.5) B32(-10.25,6.05) B33(-10.6,6.6) B34(-10.25,7.15) B35(-10.6,7.7) B36(-10.25,8.25) B37(-10.6,8.8) B38(-10.25,9.35) B39(-10.6,9.9) BA4(10.95,-9.35) BA5(11.3,-8.8) BA6(10.95,-8.25) BA7(11.3,-7.7) BA8(10.95,-7.15) BA9(11.3,-6.6) BA10(10.95,-6.05) BA11(11.3,-5.5) BA12(10.95,-4.95) BA13(11.3,-4.4) BA14(10.95,-3.85) BA15(11.3,-3.3) BA16(10.95,-2.75) BA17(11.3,-2.2) BA18(10.95,-1.65) BA19(11.3,-1.1) BA20(10.95,-0.55) BA21(11.3,0) BA22(10.95,0.55) BA23(11.3,1.1) BA24(10.95,1.65) BA25(11.3,2.2) BA26(10.95,2.75) BA27(11.3,3.3) BA28(10.95,3.85) BA29(11.3,4.4) BA30(10.95,4.95) BA31(11.3,5.5) BA32(10.95,6.05) BA33(11.3,6.6) BA34(10.95,7.15) BA35(11.3,7.7) BA36(10.95,8.25) BA37(11.3,8.8) BA38(10.95,9.35) C2(-9.9,-10.6) C3(-9.9,-9.9) C5(-9.9,-8.8) C7(-9.9,-7.7) C9(-9.9,-6.6) C11(-9.9,-5.5) C13(-9.9,-4.4) C15(-9.9,-3.3) C17(-9.9,-2.2) C19(-9.9,-1.1) C21(-9.9,0) C23(-9.9,1.1) C25(-9.9,2.2) C27(-9.9,3.3) C29(-9.9,4.4) C31(-9.9,5.5) C33(-9.9,6.6) C35(-9.9,7.7) C37(-9.9,8.8) C39(-9.9,9.9) C40(-9.9,10.6) D1(-9.35,-10.95) D2(-9.35,-10.25) D40(-9.35,10.25) D41(-9.35,10.95) E1(-8.8,-11.3) E2(-8.8,-10.6) E3(-8.8,-9.9) E39(-8.8,9.9) E40(-8.8,10.6) E41(-8.8,11.3) F1(-8.25,-10.95) F2(-8.25,-10.25) F40(-8.25,10.25) F41(-8.25,10.95) G1(-7.7,-11.3) G2(-7.7,-10.6) G3(-7.7,-9.9) G39(-7.7,9.9) G40(-7.7,10.6) G41(-7.7,11.3) H1(-7.15,-10.95) H2(-7.15,-10.25) H40(-7.15,10.25) H41(-7.15,10.95) J1(-6.6,-11.3) J2(-6.6,-10.6) J3(-6.6,-9.9) J39(-6.6,9.9) J40(-6.6,10.6) J41(-6.6,11.3) K1(-6.05,-10.95) K2(-6.05,-10.25) K40(-6.05,10.25) K41(-6.05,10.95) L1(-5.5,-11.3) L2(-5.5,-10.6) L3(-5.5,-9.9) L39(-5.5,9.9) L40(-5.5,10.6) L41(-5.5,11.3) M1(-4.95,-10.95) M2(-4.95,-10.25) M40(-4.95,10.25) M41(-4.95,10.95) N1(-4.4,-11.3) N2(-4.4,-10.6) N3(-4.4,-9.9) N39(-4.4,9.9) N40(-4.4,10.6) N41(-4.4,11.3) P1(-3.85,-10.95) P2(-3.85,-10.25) P40(-3.85,10.25) P41(-3.85,10.95) R1(-3.3,-11.3) R2(-3.3,-10.6) R3(-3.3,-9.9) R39(-3.3,9.9) R40(-3.3,10.6) R41(-3.3,11.3) T1(-2.75,-10.95) T2(-2.75,-10.25) T40(-2.75,10.25) T41(-2.75,10.95) U1(-2.2,-11.3) U2(-2.2,-10.6) U3(-2.2,-9.9) U39(-2.2,9.9) U40(-2.2,10.6) U41(-2.2,11.3) V1(-1.65,-10.95) V2(-1.65,-10.25) V40(-1.65,10.25) V41(-1.65,10.95) W1(-1.1,-11.3) W2(-1.1,-10.6) W3(-1.1,-9.9) W39(-1.1,9.9) W40(-1.1,10.6) W41(-1.1,11.3) Y1(-0.55,-10.95) Y2(-0.55,-10.25) Y40(-0.55,10.25) Y41(-0.55,10.95)
